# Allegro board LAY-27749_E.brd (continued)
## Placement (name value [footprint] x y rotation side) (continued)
R767  4.7K  [RC0402_25]  85.98 139.06 90 bottom
R768  4.7K  [RC0402_25]  85.09 139.06 90 bottom
R769  5.1  [RC0402_25]  80.77 138.28 90 bottom
R770  5.1  [RC0402_25]  116.08 138.18 180 bottom
R771  4.7K  [RC0402_25]  85.98 136.65 90 bottom
R772  4.7K  [RC0402_25]  85.09 136.65 90 bottom
R796  4.7K  [RC0402_25]  82.93 124.97 0 top
R816  0  [RC0402_25]  72.9 30.61 270 top
R817  0  [RC0603_OV]  52.78 30.61 270 top
R818  4.7K  [RC0402_25]  102.49 88.32 270 bottom
R830  10.0K  [RC0402_25]  244.6 211.84 180 bottom
R922  10.0K  [RC0402_25]  217.73 33.53 270 bottom
R923  1.5K  [RC0402_25]  218.74 33.53 90 bottom
R924  1.5K  [RC0402_25]  216.71 33.53 90 bottom
R925  10.0K  [RC0402_25]  214.68 33.53 270 bottom
R926  1.5K  [RC0402_25]  219.76 33.53 270 bottom
R927  1.5K  [RC0402_25]  215.7 33.53 270 bottom
R928  0  [RC0402_25]  213.66 33.53 270 bottom
R930  100  [RC0402_25]  212.65 33.53 270 bottom
R931  10.0K  [RC0402_25]  231.98 33.53 270 bottom
R932  1.5K  [RC0402_25]  232.99 33.53 90 bottom
R933  1.5K  [RC0402_25]  230.96 33.53 90 bottom
R934  10.0K  [RC0402_25]  228.93 33.53 270 bottom
R935  1.5K  [RC0402_25]  234.01 33.53 270 bottom
R936  1.5K  [RC0402_25]  229.94 33.53 270 bottom
R937  0  [RC0402_25]  227.91 33.53 270 bottom
R938  10.0K  [RC0402_25]  225.88 33.53 270 bottom
R939  100  [RC0402_25]  226.9 33.53 270 bottom
R940  10.0K  [RC0402_25]  246.23 33.53 270 bottom
R941  1.5K  [RC0402_25]  247.24 33.53 90 bottom
R942  1.5K  [RC0402_25]  245.21 33.53 90 bottom
R943  10.0K  [RC0402_25]  243.18 33.53 270 bottom
R944  1.5K  [RC0402_25]  248.26 33.53 270 bottom
R945  1.5K  [RC0402_25]  244.2 33.53 270 bottom
R946  0  [RC0402_25]  242.16 33.53 270 bottom
R947  10.0K  [RC0402_25]  240.13 33.53 270 bottom
R948  100  [RC0402_25]  241.15 33.53 270 bottom
R949  10.0K  [RC0402_25]  260.48 33.53 270 bottom
R950  1.5K  [RC0402_25]  259.46 33.53 90 bottom
R951  1.5K  [RC0402_25]  261.49 33.53 90 bottom
R952  10.0K  [RC0402_25]  257.43 33.53 270 bottom
R953  1.5K  [RC0402_25]  258.44 33.53 270 bottom
R954  1.5K  [RC0402_25]  262.51 33.53 270 bottom
R955  0  [RC0402_25]  256.41 33.53 90 bottom
R956  10.0K  [RC0402_25]  254.38 33.53 270 bottom
R957  100  [RC0402_25]  255.4 33.53 270 bottom
R992  330  [RC0402_25]  271.4 14.61 270 top
R993  330  [RC0402_25]  270.13 14.61 270 top
R994  330  [RC0402_25]  200.66 14.73 270 top
R995  330  [RC0402_25]  199.26 14.73 270 top
R1052  33  [RC0402_25]  70.48 31.24 180 top
R1053  33  [RC0402_25]  68.33 31.24 180 top
R1054  33  [RC0402_25]  66.17 31.24 180 top
R1055  33  [RC0402_25]  64.01 31.24 180 top
R1056  33  [RC0402_25]  61.85 31.24 180 top
R1057  33  [RC0402_25]  59.69 31.24 180 top
R1058  33  [RC0402_25]  57.53 31.24 180 top
R1059  33  [RC0402_25]  55.37 31.24 180 top
R1082  10.0K  [RC0402_25]  211.63 33.53 270 bottom
R1969  330  [RC0402_25]  279.88 85.33 180 top
R5582  1.0  [RC0805_OV]  50.11 70.13 0 bottom
R5583  1.0K  [RC0402_HD]  52.1 76.83 0 top
R5584  1.0K  [RC0402_HD]  13.32 69.39 90 bottom
R5585  1.0K  [RC0402_HD]  1.99 77.01 90 bottom
R5588  10.0K  [RC0402_25]  48.9 58.9 270 top
R5589  10.0K  [RC0402_25]  36.4 56.87 0 top
R5667  1.0K  [RC0402_HD]  49.15 70.13 90 top
R5671  1.0K  [RC0402_HD]  52.1 75.69 0 top
R5680  10.0K  [RC0402_25]  191.26 43.92 0 top
R5681  10.0K  [RC0402_25]  135.89 244.6 90 top
R5682  10.0K  [RC0402_25]  33.78 244.6 90 top
R5683  10.0K  [RC0402_25]  55.75 244.6 90 top
R5684  10.0K  [RC0402_25]  2.03 244.6 90 top
R5685  10.0K  [RC0402_25]  191.26 45.58 180 top
R5686  10.0K  [RC0402_25]  137.41 244.6 270 top
R5687  10.0K  [RC0402_25]  35.43 244.6 270 top
R5688  10.0K  [RC0402_25]  57.28 244.6 270 top
R5689  10.0K  [RC0402_25]  3.56 244.6 270 top
R5690  33K  [RC0402_25]  247.1 216.15 90 top
R5691  10.0K  [RC0402_25]  189.29 45.58 0 top
R5692  10.0K  [RC0402_25]  137.41 242.57 90 top
R5693  10.0K  [RC0402_25]  35.43 242.57 90 top
R5694  10.0K  [RC0402_25]  57.28 242.57 90 top
R5695  10.0K  [RC0402_25]  3.56 242.57 90 top
R5698  4.7K  [RC0402_25]  250.02 219.64 0 top
R5699  4.7K  [RC0402_25]  250.02 221.23 0 top
R5700  4.7K  [RC0402_25]  246.98 223.9 90 top
R5701  4.7K  [RC0402_25]  241.77 220.29 180 top
R5702  4.7K  [RC0402_25]  241.77 218.82 180 top
R5703  10.0K  [RC0402_25]  89.45 72.16 90 top
R5704  4.7K  [RC0402_25]  130.12 84.11 180 bottom
R5705  4.7K  [RC0402_25]  117.55 88.67 270 bottom
R5706  4.7K  [RC0402_25]  116.54 88.67 270 bottom
R5707  19.1  [RC0402_25]  120.73 77 270 top
R5708  19.1  [RC0402_25]  130.12 88.98 0 top
R5710  4.7K  [RC0402_25]  118.82 81.94 90 bottom
R5711  4.7K  [RC0402_25]  120.22 81.94 90 bottom
R5712  4.7K  [RC0402_25]  119.33 84.48 0 bottom
R5713  19.1  [RC0402_25]  120.98 92.61 90 top
R5721  1K  [RC0402_25]  106.02 110.53 90 top
R5722  19.1  [RC0402_25]  130.13 80.64 0 top
R5724  19.1  [RC0402_25]  117.42 92.43 90 top
R5725  17.4K  [RC0402_25]  33.15 40.39 180 top
R5726  19.1  [RC0402_25]  130.12 87.98 0 top
R5727  4.7K  [RC0402_25]  36.32 87.5 270 top
R5728  4.7K  [RC0402_25]  28.17 87.63 270 top
R5729  4.7K  [RC0402_25]  34.42 79.89 270 top
R5730  10.0K  [RC0402_25]  28.82 105.5 90 top
R5731  20K  [RC0402_25]  30.2 104.95 0 top
R5734  0  [RC0402_25]  170.46 116.2 90 top
R5735  0  [RC0402_25]  39.99 190 270 top
R5736  10.0  [RC0402_25]  32.43 162.93 90 top
R5737  12.4K  [RC0402_25]  27.39 166.57 90 top
R5739  17.4K  [RC0402_25]  28.78 166.01 0 top
R5740  10.0  [RC0402_25]  34.03 138.32 90 top
R5747  20K  [RC0402_25]  37.06 129.2 270 top
R5748  10.0K  [RC0402_25]  38.09 129.2 90 top
R5751  5K  [RC0402_25]  137.67 45.4 90 bottom
R5753  4.7K  [RC0402_25]  137.54 50.67 270 bottom
R5754  4.7K  [RC0402_25]  138.43 50.67 90 bottom
R5755  4.7K  [RC0402_25]  135.65 49.15 0 bottom
R5762  4.7K  [RC0402_25]  92.58 139.06 270 bottom
R5763  10.0  [RC0402_25]  204.81 66.01 180 top
R5766  20K  [RC0402_25]  201.18 60.97 180 top
R5767  10.0K  [RC0402_25]  201.73 62.36 90 top
R5768  10.0K  [RC0402_25]  37.06 124.07 0 top
R5769  4.7K  [RC0402_25]  56.03 84.73 90 top
R5770  4.7K  [RC0402_25]  57.35 84.73 90 top
R5771  4.7K  [RC0402_25]  82.93 123.95 180 top
R5772  10.0K  [RC0402_25]  261.24 144.53 0 top
R5773  10.0K  [RC0402_25]  261.24 145.8 0 top
R5774  10.0K  [RC0402_25]  261.24 147.07 0 top
R5775  10.0K  [RC0402_25]  261.24 148.34 0 top
R5776  10.0K  [RC0402_25]  261.24 155.45 0 top
R5777  10.0K  [RC0402_25]  261.24 156.72 0 top
R5778  10.0K  [RC0402_25]  261.24 157.99 0 top
R5779  10.0K  [RC0402_25]  261.24 159.26 0 top
R5780  10.0K  [RC0402_25]  261.24 166.37 0 top
R5781  10.0K  [RC0402_25]  261.24 167.64 0 top
R5782  10.0K  [RC0402_25]  261.24 168.91 0 top
R5783  10.0K  [RC0402_25]  261.24 170.18 0 top
R5784  10.0K  [RC0402_25]  261.24 177.29 0 top
R5785  10.0K  [RC0402_25]  261.24 178.56 0 top
R5786  10.0K  [RC0402_25]  261.24 179.83 0 top
R5787  10.0K  [RC0402_25]  261.24 181.1 0 top
R5788  33  [RC0402_25]  183.9 191.13 180 top
R5789  33  [RC0402_25]  34.68 198.75 270 top
R5790  10.0K  [RC0402_25]  245.71 223.9 270 top
R5791  0  [RC0402_25]  119.39 50.11 180 bottom
R5792  0  [RC0402_25]  161.56 50.11 180 bottom
R5793  0  [RC0402_25]  117.07 46.99 180 bottom
R5794  0  [RC0402_25]  119.11 46.23 180 bottom
R5795  0  [RC0402_25]  116.9 44.87 90 bottom
R5796  0  [RC0402_25]  114.11 44.92 0 bottom
R5797  0  [RC0402_25]  156.26 46.33 0 bottom
R5798  0  [RC0402_25]  161.27 46.23 180 bottom
R5799  0  [RC0402_25]  159.07 44.87 90 bottom
R5800  0  [RC0402_25]  156.27 44.92 0 bottom
R5801  10.0  [RC0402_25]  249.21 90.77 180 top
R5802  4.7K  [RC0402_25]  179.71 50.67 270 bottom
R5803  4.7K  [RC0402_25]  177.81 49.15 0 bottom
R5804  4.7K  [RC0402_25]  180.67 50.67 90 bottom
R5805  5K  [RC0402_25]  179.83 45.4 90 bottom
R5806  4.32K  [RC0402_25]  78.05 222.66 180 bottom
R5807  7.32K  [RC0402_25]  76.28 226.82 0 bottom
R5808  9.09k  [RC0402_25]  78.05 223.8 180 bottom
R5809  7.32K  [RC0402_25]  78.69 226.82 180 bottom
R5810  11.3K  [RC0402_25]  80.85 227.23 0 top
R5811  1.0K  [RC0402_HD]  98.94 228.97 180 top
R5812  1.0K  [RC0402_HD]  98.94 228.01 180 top
R5813  0  [RC0603_OV]  102.28 226.57 0 bottom
R5814  2.67K  [RC0402_25]  68.65 222.36 180 top
R5815  10.0K  [RC0402_25]  181.62 99.84 270 top
R5816  0  [RC0402_25]  199.53 97.56 270 top
R5817  1K  [RC0402_25]  200.77 97.56 90 bottom
R5818  1K  [RC0402_25]  197.5 97.56 270 top
R5819  1K  [RC0402_25]  197.32 114.42 90 top
R5820  1K  [RC0402_25]  201.29 114.42 90 top
R5825  1K  [RC0402_25]  183.95 82.98 90 bottom
R5826  1K  [RC0402_25]  180.67 83.01 90 bottom
R5827  1K  [RC0402_25]  180.49 99.84 270 bottom
R5828  1K  [RC0402_25]  184.46 99.84 270 bottom
R5829  1K  [RC0402_25]  183.95 82.98 270 top
R5830  1K  [RC0402_25]  180.67 83.01 270 top
R5831  1K  [RC0402_25]  180.49 99.84 90 top
R5832  1K  [RC0402_25]  184.46 99.84 90 top
R5837  1K  [RC0402_25]  200.77 97.56 270 top
R5838  1K  [RC0402_25]  197.5 97.58 90 bottom
R5839  1K  [RC0402_25]  197.32 114.42 270 bottom
R5840  1K  [RC0402_25]  201.29 114.42 270 bottom
R5847  19.1  [RC0402_25]  125.29 92.54 90 top
R5848  19.1  [RC0402_25]  126.4 92.54 90 top
R5849  19.1  [RC0402_25]  126.66 77 270 top
R5850  19.1  [RC0402_25]  125.56 77 270 top
R5851  49.9K  [RC0402_25]  95.68 37.31 0 top
R5852  49.9K  [RC0402_25]  78.53 37.08 180 top
R5853  4.7K  [RC0402_25]  69.93 144.6 0 top
R5854  4.7K  [RC0402_25]  70.09 149.35 0 top
R5855  4.7K  [RC0402_25]  70.09 148.21 0 top
R5856  4.7K  [RC0402_25]  70.09 145.92 0 top
R5857  4.7K  [RC0402_25]  70.09 147.07 0 top
R5858  10.0K  [RC0402_25]  82.95 96.42 270 top
R5870  4.7K  [RC0402_25]  241.47 120.53 90 top
R5871  4.7K  [RC0402_25]  244.74 120.53 90 top
R5872  4.7K  [RC0402_25]  241.15 132.59 270 top
R5873  4.7K  [RC0402_25]  237.87 132.59 270 top
R5874  4.7K  [RC0402_25]  238.96 132.59 270 top
R5875  10.0K  [RC0402_25]  112.65 139.06 270 bottom
R5876  200  [RC0402_25]  109.33 143.69 180 bottom
R5877  200  [RC0402_25]  109.35 144.69 180 bottom
R5878  200  [RC0402_25]  106.33 141.69 0 bottom
R5879  200  [RC0402_25]  106.33 142.69 0 bottom
R5880  200  [RC0402_25]  105.33 143.7 0 bottom
R5881  200  [RC0402_25]  105.33 144.69 0 bottom
R5882  200  [RC0402_25]  105.92 138.43 90 bottom
R5883  200  [RC0402_25]  104.9 138.43 90 bottom
R5884  200  [RC0402_25]  91.33 181.69 0 bottom
R5885  200  [RC0402_25]  91.33 180.7 0 bottom
R5886  200  [RC0402_25]  92.33 183.69 180 bottom
R5887  200  [RC0402_25]  92.33 182.73 180 bottom
R5888  200  [RC0402_25]  90.33 183.69 180 bottom
R5889  200  [RC0402_25]  90.33 182.73 180 bottom
R5890  200  [RC0402_25]  105.83 154.2 270 bottom
R5891  200  [RC0402_25]  104.81 153.19 270 bottom
R5892  10.0K  [RC0402_25]  244.56 223.9 270 top
R5893  9.88K  [RC0402_25]  30.38 141.4 0 top
R5894  12.4K  [RC0402_25]  28.99 141.95 270 top
R5895  0  [RC0402_25]  103.03 95.23 90 top
R5896  0  [RC0402_25]  114.98 95.67 270 top
R5897  4.7K  [RC0402_25]  58.8 84.73 90 top
R5898  4.7K  [RC0402_25]  81.28 124.46 90 top
R5902  4.7K  [RC0402_25]  80.01 124.46 90 top
R5903  4.7K  [RC0402_25]  78.61 124.46 90 top
R5904  4.7K  [RC0402_25]  77.34 124.46 90 top
R5905  0  [RC0402_25]  170.46 114.17 90 top
R5906  0  [RC0402_25]  41.66 190.5 180 top
R5907  4.7K  [RC0402_25]  273.41 76.92 270 top
SW1  416131160804  [SW4_DIP_1P27_6P3X5P7]  267.46 146.43 90 top
SW2  416131160804  [SW4_DIP_1P27_6P3X5P7]  267.46 157.35 90 top
SW3  416131160804  [SW4_DIP_1P27_6P3X5P7]  267.46 168.28 90 top
SW4  416131160804  [SW4_DIP_1P27_6P3X5P7]  267.46 179.2 90 top
SW5  SPL6BLH  [SW6_TACT_LED_TH]  17.75 17.3 90 top
SW6  TL1105SF160Q  [SW2_TL1105S]  5.76 3.72 0 top
TP1  TPAD_020  [TPAD_020_TOP]  76.33 154.94 90 top
TP2  TPAD_020  [TPAD_020_TOP]  75.31 153.8 90 top
TP3  TPAD_020  [TPAD_020_TOP]  75.84 151.79 90 top
TP4  TPAD_020  [TPAD_020_TOP]  71.92 151.17 90 top
TP5  TPAD_020  [TPAD_020_TOP]  74.42 150.83 0 top
TP6  TPAD_020  [TPAD_020_TOP]  68.45 148.84 0 top
TP7  TPAD_020  [TPAD_020_TOP]  68.45 147.57 0 top
TP8  TPAD_020  [TPAD_020_TOP]  68.45 146.43 0 top
TP9  TPAD_020  [TPAD_020_TOP]  68.45 145.29 0 top
TP10  TPAD_020  [TPAD_020_TOP]  75.69 148.84 0 top
TP11  TPAD_020  [TPAD_020_TOP]  74.55 148.84 0 top
TP13  TPAD_020  [TPAD_020_TOP]  74.3 143.76 90 top
TP14  TPAD_020  [TPAD_020_TOP]  75.69 143.76 0 top
TP15  TPAD_020  [TPAD_020_TOP]  80.9 138.94 0 top
TP16  TPAD_020  [TPAD_020_TOP]  82.17 138.94 0 top
TP18  TPAD_020  [TPAD_020_TOP]  87.12 138.94 90 top
TP19  TPAD_020  [TPAD_020_TOP]  88.39 138.94 0 top
TP20  TPAD_020  [TPAD_020_TOP]  80.9 137.54 0 top
TP21  TPAD_020  [TPAD_020_TOP]  82.17 137.54 0 top
TP22  TPAD_020  [TPAD_020_TOP]  84.07 137.54 0 top
TP72  TPAD_020  [TPAD_020_TOP]  80.9 42.75 0 top
TP73  TPAD_020  [TPAD_020_TOP]  95.82 174.69 180 bottom
TP74  TPAD_020  [TPAD_020_TOP]  90.81 174.69 0 bottom
TP75  TPAD_020  [TPAD_020_TOP]  104.84 173.74 90 bottom
TP76  TPAD_020  [TPAD_020_TOP]  101.85 173.74 90 bottom
TP77  TPAD_020  [TPAD_020_TOP]  99.82 173.74 0 bottom
TP78  TPAD_020  [TPAD_020_TOP]  108.84 173.69 180 bottom
TP79  TPAD_020  [TPAD_020_TOP]  96.84 173.67 270 bottom
TP80  TPAD_020  [TPAD_020_TOP]  94.81 173.67 180 bottom
TP81  TPAD_020  [TPAD_020_TOP]  92.84 173.67 180 bottom
TP82  TPAD_020  [TPAD_020_TOP]  109.86 172.69 180 bottom
TP83  TPAD_020  [TPAD_020_TOP]  89.79 166.7 180 bottom
TP84  TPAD_020  [TPAD_020_TOP]  89.82 158.69 180 bottom
TP86  TPAD_020  [TPAD_020_TOP]  79.96 153.85 180 bottom
TP88  TPAD_020  [TPAD_020_TOP]  106.32 148.54 180 bottom
TP89  TPAD_020  [TPAD_020_TOP]  94.81 152.72 180 bottom
TP90  TPAD_020  [TPAD_020_TOP]  108.84 152.65 270 bottom
TP91  TPAD_020  [TPAD_020_TOP]  106.82 151.7 180 bottom
TP92  TPAD_020  [TPAD_020_TOP]  103.82 151.7 180 bottom
TP93  TPAD_020  [TPAD_020_TOP]  97.92 151.69 180 bottom
TP94  TPAD_020  [TPAD_020_TOP]  95.89 151.69 180 bottom
TP95  TPAD_020  [TPAD_020_TOP]  100.84 151.64 180 bottom
TP96  TPAD_020  [TPAD_020_TOP]  110.81 150.69 270 bottom
TP97  TPAD_020  [TPAD_020_TOP]  93.79 150.74 180 bottom
TP98  TPAD_020  [TPAD_020_TOP]  111.82 149.73 270 bottom
TP99  TPAD_020  [TPAD_020_TOP]  109.86 149.67 270 bottom
TP100  TPAD_020  [TPAD_020_TOP]  108.84 146.69 180 bottom
TP101  TPAD_020  [TPAD_020_TOP]  85.86 145.67 180 bottom
TP103  TPAD_020  [TPAD_020_TOP]  86.74 142.49 180 bottom
TP115  TPAD_020  [TPAD_020_TOP]  276.32 84.57 0 top
TP192  TPAD_020  [TPAD_020_TOP]  47.93 74.47 0 top
TP193  TPAD_020  [TPAD_020_TOP]  49.2 71.93 0 top
TP194  TPAD_020  [TPAD_020_TOP]  47.93 73.2 0 top
TP195  TPAD_020  [TPAD_020_TOP]  49.2 73.2 0 top
TP196  TPAD_020  [TPAD_020_TOP]  62.03 65.84 0 top
TP197  TPAD_020  [TPAD_020_TOP]  47.93 71.93 0 top
TP200  TPAD_020  [TPAD_020_TOP]  79.38 100.3 90 top
TP201  TPAD_020  [TPAD_020_TOP]  80.04 101.42 90 top
TP202  TPAD_020  [TPAD_020_TOP]  80.75 100.3 90 top
TP203  TPAD_020  [TPAD_020_TOP]  81.41 101.42 90 top
TP204  TPAD_020  [TPAD_020_TOP]  82.12 100.3 90 top
TP205  TPAD_020  [TPAD_020_TOP]  86.87 145.8 180 bottom
TP206  TPAD_020  [TPAD_020_TOP]  93.34 137.01 180 bottom
TP208  TPAD_020  [TPAD_020_TOP]  127.97 90.07 0 top
TP209  TPAD_020  [TPAD_020_TOP]  118.75 73.81 0 top
TP210  TPAD_020  [TPAD_020_TOP]  115.27 89.05 0 top
TP212  TPAD_020  [TPAD_020_TOP]  113.51 107.29 0 top
TP213  TPAD_020  [TPAD_020_TOP]  72.39 148.92 0 top
TP214  TPAD_020  [TPAD_020_TOP]  129.12 90.02 0 top
TP215  TPAD_020  [TPAD_020_TOP]  23.16 232.82 0 top
TP216  TPAD_020  [TPAD_020_TOP]  24.81 234.09 0 top
TP217  TPAD_020  [TPAD_020_TOP]  30 99.44 0 top
TP218  TPAD_020  [TPAD_020_TOP]  28.57 160.5 0 top
TP219  TPAD_020  [TPAD_020_TOP]  30.18 135.89 0 top
TP222  TPAD_020  [TPAD_020_TOP]  93.17 83.39 0 top
TP223  TPAD_020  [TPAD_020_TOP]  140.19 46.93 180 top
TP224  TPAD_020  [TPAD_020_TOP]  140.72 45.84 180 top
TP225  TPAD_020  [TPAD_020_TOP]  140.19 50.93 180 top
TP226  TPAD_020  [TPAD_020_TOP]  140.19 52.7 180 top
TP227  TPAD_020  [TPAD_020_TOP]  140.95 54.01 180 top
TP228  TPAD_020  [TPAD_020_TOP]  140.95 51.83 180 top
TP229  TPAD_020  [TPAD_020_TOP]  140.19 54.86 180 top
TP230  TPAD_020  [TPAD_020_TOP]  118.97 60.68 180 top
TP231  TPAD_020  [TPAD_020_TOP]  118.63 59.27 180 top
TP232  TPAD_020  [TPAD_020_TOP]  117.99 60.26 180 top
TP233  TPAD_020  [TPAD_020_TOP]  114.54 56.04 180 top
TP234  TPAD_020  [TPAD_020_TOP]  114.54 52.87 180 top
TP235  TPAD_020  [TPAD_020_TOP]  113.65 53.53 180 top
TP236  TPAD_020  [TPAD_020_TOP]  114.54 54.29 180 top
TP237  TPAD_020  [TPAD_020_TOP]  113.65 54.98 180 top
TP238  TPAD_020  [TPAD_020_TOP]  114.54 49.29 180 top
TP239  TPAD_020  [TPAD_020_TOP]  113.65 50.07 180 top
TP240  TPAD_020  [TPAD_020_TOP]  114.54 51.16 180 top
TP241  TPAD_020  [TPAD_020_TOP]  113.65 51.91 180 top
TP242  TPAD_020  [TPAD_020_TOP]  114.54 46.74 180 top
TP243  TPAD_020  [TPAD_020_TOP]  113.65 47.33 180 top
TP244  TPAD_020  [TPAD_020_TOP]  114.54 47.97 180 top
TP245  TPAD_020  [TPAD_020_TOP]  113.54 48.92 180 top
TP246  TPAD_020  [TPAD_020_TOP]  207.24 62.16 90 top
TP249  TPAD_020  [TPAD_020_TOP]  248.52 156.64 0 top
TP252  TPAD_020  [TPAD_020_TOP]  78.45 103.43 90 top
TP253  TPAD_020  [TPAD_020_TOP]  72.73 103.43 90 top
TP254  TPAD_020  [TPAD_020_TOP]  73.91 103.43 90 top
TP255  TPAD_020  [TPAD_020_TOP]  75.02 103.43 90 top
TP256  TPAD_020  [TPAD_020_TOP]  76.16 103.43 90 top
TP257  TPAD_020  [TPAD_020_TOP]  77.3 103.43 90 top
TP258  TPAD_020  [TPAD_020_TOP]  81.19 134.7 90 top
TP259  TPAD_020  [TPAD_020_TOP]  65.79 83.44 0 top
TP260  TPAD_020  [TPAD_020_TOP]  251.64 86.92 90 top
TP261  TPAD_020  [TPAD_020_TOP]  182.35 46.93 180 top
TP262  TPAD_020  [TPAD_020_TOP]  182.88 45.84 180 top
TP263  TPAD_020  [TPAD_020_TOP]  182.35 50.93 180 top
TP264  TPAD_020  [TPAD_020_TOP]  182.35 52.7 180 top
TP265  TPAD_020  [TPAD_020_TOP]  183.12 54.01 180 top
TP266  TPAD_020  [TPAD_020_TOP]  183.12 51.83 180 top
TP267  TPAD_020  [TPAD_020_TOP]  182.35 54.86 180 top
TP268  TPAD_020  [TPAD_020_TOP]  156.7 46.74 180 top
TP269  TPAD_020  [TPAD_020_TOP]  155.81 47.33 180 top
TP270  TPAD_020  [TPAD_020_TOP]  156.7 47.97 180 top
TP271  TPAD_020  [TPAD_020_TOP]  155.68 48.82 180 top
TP272  TPAD_020  [TPAD_020_TOP]  156.7 49.29 180 top
TP273  TPAD_020  [TPAD_020_TOP]  155.81 50.07 180 top
TP274  TPAD_020  [TPAD_020_TOP]  156.7 51.16 180 top
TP275  TPAD_020  [TPAD_020_TOP]  155.81 51.85 180 top
TP276  TPAD_020  [TPAD_020_TOP]  156.7 52.87 180 top
TP277  TPAD_020  [TPAD_020_TOP]  155.81 53.53 180 top
TP278  TPAD_020  [TPAD_020_TOP]  156.7 54.29 180 top
TP279  TPAD_020  [TPAD_020_TOP]  155.81 54.98 180 top
TP280  TPAD_020  [TPAD_020_TOP]  156.7 56.04 180 top
TP281  TPAD_020  [TPAD_020_TOP]  160.15 60.26 180 top
TP282  TPAD_020  [TPAD_020_TOP]  160.79 59.27 180 top
TP283  TPAD_020  [TPAD_020_TOP]  161.14 60.68 180 top
TP284  TPAD_020  [TPAD_020_TOP]  112.09 141.55 180 bottom
TP285  TPAD_020  [TPAD_020_TOP]  112.65 140.67 180 bottom
TP286  TPAD_020  [TPAD_020_TOP]  132.92 237.52 0 top
TP287  TPAD_020  [TPAD_020_TOP]  108.52 95.22 90 top
TP288  TPAD_020  [TPAD_020_TOP]  109.49 95.68 270 top
TP289  TPAD_020  [TPAD_020_TOP]  275.18 84.57 0 top
TP290  TPAD_020  [TPAD_020_TOP]  50.24 68.2 0 top
U1  AP62600SJ-7  [QFN12_0P5_2P05X3P05MM]  31.04 102.16 180 top
U2  ADT7481ARMZ  [MSOP10_60X12]  249.05 232.92 0 top
U3  LTC3882  [QFN40_0P5_6P1X6P1]  83.39 222.66 90 bottom
U7  SIC620ACD-T1-GE3  [POWERPAK_MLP55]  94.43 230.99 180 top
U9  SIC620ACD-T1-GE3  [POWERPAK_MLP55]  76.35 231.36 180 top
U14  MP20073DH  [MSOP8_0P65_3P1X3P1_EPAD]  34.54 194.18 90 top
U16  PCF2131  [SO16_0P5_3P5X4P5_MM]  277.34 81.02 270 top
U17  MP20073DH  [MSOP8_0P65_3P1X3P1_EPAD]  179.33 191.27 0 top
U18  PCA9517ADP  [TSSOP8_A]  246.63 204.6 180 top
U22  T4240NSE7TTB  [BGA1932_1MM_45X45MM]  100.33 163.19 180 top
U23  AP62600SJ-7  [QFN12_0P5_2P05X3P05MM]  29.62 163.22 180 top
U25  AP62600SJ-7  [QFN12_0P5_2P05X3P05MM]  31.22 138.61 180 top
U26  SST25WF040B  [SO8_1P27_4X5]  86.16 132.41 180 top
U27  M2GL005-VFG256  [BGA256_0P8_14X14MM_C016S]  61.07 74.8 180 top
U32  SI53258  [QFN40_0P5_6X6_4P6EP]  108.2 105.23 180 top
U36  Si5341B-D15390-GM  [QFN64_0P5_9X9C]  122 84.73 0 top
U37  S29GL01GT11TFIV10  [TSOP56_0P5_14X18]  84.2 84.2 270 top
U38  MT29F8G08ABBCAH4-IT:C  [VFBGA63_0P8_9X11]  99.69 83.82 0 top
U42  88E1543A1LKJ2C000T123  [LQFP128_0P5_20X14_EPAD]  127.38 49.66 0 top
U45  NVT4858HK  [XQFN16_0P4_2P7X1P9]  83.82 42.37 180 top
U46  LTC2804  [DFN16_0P5_3X5]  66.29 36.57 90 top
U47  NX5P3090UK  [WLCSP12_0P4_1P38X1P68MM_SMDP]  43.18 42.04 270 top
U48  NX5P3090UK  [WLCSP12_0P4_1P38X1P68MM_SMDP]  33.15 42.04 270 top
U55  PCIE-LP-04-01-F-DV-A-K-TR  [CON64_1MM_SM_PCIE_LP]  221.72 215.15 270 top
U58  PCA9517ADP  [TSSOP8_A]  246.51 210.82 180 top
U65  DS100DF410  [QFN48_0P5_7X7_EP5P1]  182.37 90.81 180 top
U68  AP62600SJ-7  [QFN12_0P5_2P05X3P05MM]  248.92 87.96 270 top
U69  AP62600SJ-7  [QFN12_0P5_2P05X3P05MM]  204.52 63.2 270 top
U82  PCA9547PW  [TSSOP24_0P65_7P9X4P5]  240.05 126.5 90 top
U95  LTC2804  [DFN16_0P5_3X5]  57.66 36.63 90 top
U105  EMC2305  [TQFN16_0P65_4X4MM_TAB]  245.96 219.96 0 top
U250  SST25LF080  [SO8-25X75-200]  42.98 57.51 270 top
U589  24AA025UID-I/SN  [SO8_1P27_4X5]  246.68 197.23 180 top
U593  74ALVCH16373DGGRG4  [TSSOP48_PH]  86.77 110.79 90 top
U594  74ALVCH16373DGGRG4  [TSSOP48_PH]  72.03 110.79 90 top
U595  74LVC1G86GW-Q100  [SC70-5]  90.35 101.24 180 top
U596  74LVC1G86GW-Q100  [SC70-5]  87.38 101.24 180 top
U598  74LVC1G86GW-Q100  [SC70-5]  84.37 101.24 180 top
U605  RT9013-33GQW  [DFN6_0P65_2X2_EP]  35.05 84.96 180 top
U606  RT9013-18GB  [SOT-23-5]  29.31 84.58 180 top
U607  RT9078-12GJ5_5P  [SOT23-5]  35.56 76.58 180 top
U608  PUSB3AB4  [XSON10_0P5_1P1X2P6MM]  42.02 17.14 90 top
U610  PCA9701  [TSSOP_24_0P65_8X4]  253.23 162.91 90 top
U620  88E1543A1LKJ2C000T123  [LQFP128_0P5_20X14_EPAD]  169.54 49.66 0 top
U622  DS100DF410  [QFN48_0P5_7X7_EP5P1]  199.2 105.38 180 top
U624  PCA9671BS  [QFN24_4X4_EP2P25MM]  250.27 111.68 180 top
U625  24AA025UID-I/SN  [SO8_1P27_4X5]  246.63 190.75 180 top
U626  SI53361-B-GM  [QFN16_0P5_3X3MM]  105.69 95.47 90 top
U627  SI53361-B-GM  [QFN16_0P5_3X3MM]  112.32 95.43 270 top
U628  74AUP1G04GV  [SOT23-5_A]  44.45 46.99 90 top
U629  74AUP1G04GV  [SOT23-5_A]  34.42 46.99 90 top
U630  MAX8902B  [TDFN8_1P98_2P10X2P10]  36.31 126.33 90 top
U631  LTC7150S  [BGA42_0P8_5X6]  28.29 228.47 0 top
Y7  7M48072002  [XTAL_4_3P3X2P6MM]  112.85 85.24 270 top
Y19  16MHz  [XTAL4_2P1X1P7]  50.88 80.77 90 top
Y20  25MHZ  [XTAL2_3P3X2P6]  143.64 48.65 90 top
Y21  25MHZ  [XTAL2_3P3X2P6]  185.8 48.65 90 top

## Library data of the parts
BH9 BH10 = MOUNT_HOLE: room: VDD_GVDD_PS
C1-C6 C8-C10 C12 C15-C18 C83 C84 C89 C105 C120-C123 C125 C133-C136 C143 C148 C151 C169 C170 C173 C199 C205 C207 C250 C252 C253 C256 C258-C263 C265 C268-C271 C273-C275 C280-C286 C288 C305 C334 C341 C412 C434 C467 C472 C485 C546-C557 C562-C573 C588 C592 C604 C607-C611 C614 C616-C620 C624 C627 C628 C638 C650 C691 C709 C710 C715-C717 C728 C782 C800 C802 C821 C822 C833 C837 C839 C841-C845 C847 C859 C860 C867 C868 C871 C877-C880 C900 C987 C991-C993 C1002 C1109-C1113 C1141-C1152 C1224-C1227 C1229-C1232 C1240-C1243 C1247 C1250-C1254 C1256 C1257 C1259-C1266 C2673 C2679 C2680 C3690 C3691 C3744 C3745 C3844 C3847 C3849-C3856 C3860-C3870 C3889-C3892 C3894 C3895 C3897-C3900 C5116-C5121 C5125 C5126 C5131 C5133 C5134 C5136-C5168 C5171 C5174-C5176 C5178-C5211 C5213-C5259 C5270-C5272 C5302-C5309 C5312-C5321 C5327-C5330 C5333 C5334 = CAP_NP
C7 C25-C28 C35 C40-C43 C58 C60 C65 C66 C76 C78-C82 C88 C90 C95 C96 C102-C104 C106 C108 C112 C113 C117-C119 C126 C128-C130 C137 C141 C144 C145 C147 C149 C152 C153 C158 C159 C162-C168 C171 C172 C176 C179 C182 C185-C187 C189 C190 C197 C201 C202 C208 C211 C215 C216 C220 C221 C224-C231 C240 C255 C276 C296 C297 C299 C300 C303 C304 C309 C310 C332 C345-C347 C433 C443-C458 C481 C482 C505 C515 C516 C518-C520 C522 C523 C574 C575 C578 C586 C594 C615 C629-C631 C635 C640-C642 C647-C649 C653 C656 C658-C664 C666 C667 C669-C676 C678 C679 C681-C688 C690 C694-C701 C703 C704 C706 C707 C711-C713 C720-C726 C729-C737 C744-C752 C754 C756-C764 C770-C781 C788-C796 C804-C806 C819 C825 C827 C828 C831 C832 C834 C838 C840 C848 C869 C924 C932 C936 C940 C944 C947 C950 C961 C965 C996-C1001 C1031-C1038 = CAP_NP: signal model: M-C0402B_0.1UF/16V
C85 C94 C127 = CAP_NP: tolerance: 10%; signal model: M-C0402B_0.1UF/16V; room: VDD_GVDD_PS
C86 C87 C93 C97 C101 C124 C2636 C2637 C5260 C5269 C5273 C5274 C5276 C5285 C5286 C5343 C5344 = CAP_NP: tolerance: 10%; room: VDD_GVDD_PS
C91 C107 C5261-C5264 C5280 C5290 = CAP_NP: room: XVDD_SVDD_PS
C92 C5291 = CAP_NP: tolerance: 20%; room: FPGA
C98 C99 C115 C116 C131 C5127-C5130 C5266 C5275 C5277 C5278 C5284 C5287 C5288 = CAP_NP: room: VDD_GVDD_PS
C109 C110 C5292-C5301 = CAP_NP: tolerance: 10%; room: PEX_SLOTS123_REFCLK
C114 = CAP_NP: tolerance: 20%; signal model: M-C0402B_0.1UF/16V; room: FPGA
C138 C150 C157 C161 C191 C192 C196 C209 C218 C246 C251 C295 C576 C577 C579-C585 C587 C590 C591 C593 C595-C603 C605 C606 C612 C613 C621-C623 C625 C626 C632-C634 C636 C637 C639 C643-C646 C651 C652 C654 C655 C657 C665 C668 C677 C680 C689 C692 C693 C702 C705 C708 C714 C718 C719 C727 C741-C743 C753 C755 C765 C766 C786 C787 C801 C803 C807-C813 C817 C818 C823 C824 C829 C830 C835 C836 C846 C849-C858 C861-C866 C870 C872-C876 = CAP_NP: signal model: M-C0402_0.1UF
C254 C5135 = CAP_NP: tolerance: 10%
C402 C406 C422 C425 = CAP_NP: signal model: M-C0402_0.01UF/16V
C1158 = CAP_NP: room: DUT_CLOSE
C1208-C1223 = CAP_NP: signal model: M-C0402B_0.01UF/50V
C2704 C2705 = CAP_NP: tolerance: 10%; room: DUT_CLOSE
C3697 C3742 C3743 = CAP_NP: room: GVDD_PS
C3698-C3700 C3831 = CAP_NP: room: 1V5_SB
C3701-C3703 C3710-C3714 C3716-C3725 C3728-C3739 C3836-C3843 = CAP_NP: Tolerance: TOLERANCE; User Part Number: 150-79872; room: 1V5_SB
C3747 = CAP_NP: room: SWITCHES
C3848 = CAP_NP: alternate symbols: (CC0402_HD); room: I2C1
C3857 C3859 = CAP_NP: tolerance: 10%; room: SDHC
C3858 C3893 C3896 = CAP_NP: tolerance: 10%; room: RS232
C3873 C3874 C3881 C3882 C5310 C5311 = CAP_NP: room: MII_MUX
C5122 C5345 CT24 CT28-CT32 CT35 CT40-CT48 CT54 CT55 = CAP_POL
C5123 C5124 C5265 C5267 C5268 C5279 C5281-C5283 C5289 C5337-C5342 = CAP_POL: room: VDD_GVDD_PS
C5132 = CAP_NP: tolerance: 5%
C5324 = CAP_NP: alternate symbols: (CC0402_HD); room: XFI
CN3 = CONN_SDCARD_PUSH_PULL_9P_SH2
CN4 = CON_USB_8P_F_4SH
D9 D10 = DIODE
D46 = DIODE_SCHTKY
ESD1-ESD10 = DIODE_TVS_BIDIR
F1 = FUSE_RESETTABLE
FAN1-FAN5 FAN12 = CON_HDR_1X4
FB1 FB23 FB87 FB89-FB93 FB95-FB99 L1 L7 L54-L57 = INDUCTOR
FB9-FB12 FB16-FB20 FB24-FB26 FB47-FB56 FB101 = BEAD_FERRITE
FB38 FB70-FB72 FB81 FB84 FB86 L26 L27 L29-L32 = BEAD
FL6 = EMIFILTER_CC
FL13-FL26 = NFM18PC225B1A3
H1-H16 = MOUNTING_HOLE_ATX_6P
J2 = CONN_SHRHDR_8X2
J3 = CONN_PCI_EXPRESS_X8
J4 J55 JP7 JP8 = CONN_HDR_3X1
J5-J7 = DDR3_240P
J8 = ATX_12V_PWR_CONN8: room: ATX_POWER
J9 = CONN_PWR_12X2
J10 = CON_SATA_PLUG7
J11-J14 = RJ45_MAG_2X1_LED
J16 = CON_SFPCAGE_1X4
J69 = CONN_HDR_5X1
J105 = HTST-105-01-S-DV: room: FPGA
J106 = CON12_98414_PMBUS: room: VDD_GVDD_PS
L3 = INDUCTOR: tolerance: 20%; room: VDD_GVDD_PS
L4 L5 = ETQP6F_2P: tolerance: 10%; room: VDD_GVDD_PS
L23 L24 = 42H171000: signal model: M-CHOKE2X1_2A_90E/350MA
L52 L53 = INDUCTOR: tolerance: 20%; room: RS232
LAN1 = CON16_RJ45_JACK
LED1-LED4 = LED
LED5 LED6 = LED_DUAL_GG
Q1 Q2 = PNP: room: VDD_GVDD_PS
Q3-Q13 = NMOS_NX3008NBK
R1-R3 R55 R56 R67-R74 R93 R97 R100 R102 R113 R119 R120 R124 R125 R128 R142 R143 R145 R146 R151 R175 R178 R179 R182 R191 R197-R200 R202 R206 R211 R213 R217-R219 R221 R222 R224 R229 R230 R232-R234 R250-R255 R257-R271 R273 R276-R280 R285 R291 R294 R295 R297-R299 R306-R310 R313 R314 R317 R319-R323 R332 R333 R335-R338 R341 R508 R524 R525 R532-R539 R641-R652 R654-R656 R659-R666 R671 R672 R685-R687 R689-R691 R693-R697 R699-R701 R706-R710 R712 R714-R718 R720 R722 R725-R727 R730-R748 R750 R751 R753 R756-R759 R762-R772 R796 R816-R818 R830 R922-R928 R930-R957 R992-R995 R1052-R1059 R1082 R5690 R5703 R5707 R5708 R5713 R5721 R5722 R5724-R5729 R5731 R5736 R5737 R5739 R5740 R5747 R5751 R5753-R5755 R5762 R5763 R5766 R5769-R5805 R5815-R5820 R5825-R5832 R5837-R5840 R5847-R5850 R5853-R5858 R5876-R5898 R5902-R5906 = RES
R30 R35 R36 R51 = RES: room: I2C1_CH2
R40 R41 R44 R57 R58 R65 R66 R76 R77 R95 R98 R99 R101 R103 R632 R5583-R5585 R5667 R5671 R5734 R5735 R5811 R5812 = RES: tolerance: 5%; room: VDD_GVDD_PS
R42 R43 R47-R50 R60-R64 R75 R78 R92 R629 R5582 R5806-R5810 R5813 R5814 = RES: room: VDD_GVDD_PS
R46 R53 R54 = RES: tolerance: 1%; room: VDD_GVDD_PS
R52 R627 R630 R631 = RES: tolerance: 5%; room: VDD_GVDD_PS; signal model: M-R0402_0E
R59 = RES: room: ATX PS
R96 R5730 R5748 R5767 R5768 R5875 = RES: room: 1V5_SB
R104 R5851 R5852 = RES: room: PS_VDD_GVDD
R176 R177 R180 R181 R311 R312 R315 R316 R318 R698 R703 R705 R711 R713 = RES: signal model: M-R0402_0
R190 R192 R196 R203 R205 R208 = RES: signal model: M-R0402B
R296 R301 = RES: signal model: M-R0402_33
R342 R637 R667 R669 R670 = RES: signal model: M-R0402_100
R394 = RES: signal model: M-R0402_27
R519-R523 R526-R528 R530 R531 R5704-R5706 R5710-R5712 R5870-R5874 = RES: tolerance: 1%; room: DUT_CLOSE
R529 = RES: tolerance: 1%; room: DUT_CLOSE; signal model: M-R0402_0E
R614 = RES: signal model: M-R0402_33E
R628 = RES: room: VDD_GVDD_PS; signal model: M-R0402_0E
R761 = RES: signal model: M-R0402_0E
R1969 = RES: tolerance: 5%
R5588 R5589 = RES: tolerance: 1%; room: FPGA
R5680-R5689 R5691-R5695 = RES: room: MII_MUX
R5698-R5702 = RES: tolerance: 1%
R5907 = RES: room: FPGA
SW1-SW4 = SW_DIP4
SW5 = SPL6BL_SW6_TACT
SW6 = SW_TACT-SPST-2_SM1
TP1-TP11 TP13-TP16 TP18-TP22 TP72-TP84 TP86 TP88-TP101 TP103 TP115 TP192-TP197 TP200-TP206 TP208-TP210 TP212-TP219 TP222-TP246 TP249 TP252-TP290 = T POINT TH
U1 U23 U25 U68 U69 = AP62600SJ
U2 = ADT7481
U3 = LTC3882_40P_EP: room: VDD_GVDD_PS
U7 U9 = SIC620ACD_MLP55
U14 U17 = MP20073DH_8P_EP
U16 = PCF2131
U18 U58 = PCA9507DP_TSSOP8
U22 = T4240
U26 = SST25WF040B_SOIC8
U27 = M2GL005_VFG256
U32 = Si53258
U36 = Si5341B_64P_EP
U37 = S29GL01GP
U38 = MT29F4G08ABBDAH4
U42 U620 = IC_88E1543_LQFP_128P_EP
U45 = NVT4858HK_QFN16
U46 U95 = LTC2804IDHC
U47 U48 = NX5P3090UK_WLCSP12
U55 = CONN_PCIEXP_64P_CUST_B
U65 U622 = DS100RT410_48P
U82 = PCA9547_24P: room: XFI
U105 = EMC2305_16P_EP
U250 = SST25LF080A
U589 U625 = 24AA025E_EEPROM_8P
U593 U594 = 74ALVCH16373DGGRG4
U595 U596 U598 = 74AUP1G86GW
U605 = RT9013_DFN6_EP
U606 = NCP561
U607 = RT9078-12GJ5_5p
U608 = DIODE_ESD_4CH_PUSB3AB4
U610 = PCA9701PW_24: room: SWITCHES
U624 = PCA9671BS_HVQFN24
U626 U627 = SI53361
U628 U629 = 74AUP1G04GV
U630 = MAX8902B: room: VDD_LP_PS
U631 = LTC7150_BGA42
Y7 = XTAL_13Y
Y19 = XTAL_13
Y20 Y21 = XTAL

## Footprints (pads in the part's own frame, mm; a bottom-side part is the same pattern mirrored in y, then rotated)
1206_CC
  rect 0.94x1.702 smd: 1(-1.4,0) 2(1.4,0)
BGA42_0P8_5X6
  round 0.406 smd: A1(-2,2.4) A2(-1.2,2.4) A3(-0.4,2.4) A4(0.4,2.4) A5(1.2,2.4) A6(2,2.4) B1(-2,1.6) B2(-1.2,1.6) B3(-0.4,1.6) B4(0.4,1.6) B5(1.2,1.6) B6(2,1.6) C1(-2,0.8) C2(-1.2,0.8) C3(-0.4,0.8) C4(0.4,0.8) C5(1.2,0.8) C6(2,0.8) D1(-2,0) D2(-1.2,0) D3(-0.4,0) D4(0.4,0) D5(1.2,0) D6(2,0) E1(-2,-0.8) E2(-1.2,-0.8) E3(-0.4,-0.8) E4(0.4,-0.8) E5(1.2,-0.8) E6(2,-0.8) F1(-2,-1.6) F2(-1.2,-1.6) F3(-0.4,-1.6) F4(0.4,-1.6) F5(1.2,-1.6) F6(2,-1.6) G1(-2,-2.4) G2(-1.2,-2.4) G3(-0.4,-2.4) G4(0.4,-2.4) G5(1.2,-2.4) G6(2,-2.4)
BGA256_0P8_14X14MM_C016S
  round 0.406 smd: A1(-6,6) A2(-5.2,6) A3(-4.4,6) A4(-3.6,6) A5(-2.8,6) A6(-2,6) A7(-1.2,6) A8(-0.4,6) A9(0.4,6) A10(1.2,6) A11(2,6) A12(2.8,6) A13(3.6,6) A14(4.4,6) A15(5.2,6) A16(6,6) B1(-6,5.2) B2(-5.2,5.2) B3(-4.4,5.2) B4(-3.6,5.2) B5(-2.8,5.2) B6(-2,5.2) B7(-1.2,5.2) B8(-0.4,5.2) B9(0.4,5.2) B10(1.2,5.2) B11(2,5.2) B12(2.8,5.2) B13(3.6,5.2) B14(4.4,5.2) B15(5.2,5.2) B16(6,5.2) C1(-6,4.4) C2(-5.2,4.4) C3(-4.4,4.4) C4(-3.6,4.4) C5(-2.8,4.4) C6(-2,4.4) C7(-1.2,4.4) C8(-0.4,4.4) C9(0.4,4.4) C10(1.2,4.4) C11(2,4.4) C12(2.8,4.4) C13(3.6,4.4) C14(4.4,4.4) C15(5.2,4.4) C16(6,4.4) D1(-6,3.6) D2(-5.2,3.6) D3(-4.4,3.6) D4(-3.6,3.6) D5(-2.8,3.6) D6(-2,3.6) D7(-1.2,3.6) D8(-0.4,3.6) D9(0.4,3.6) D10(1.2,3.6) D11(2,3.6) D12(2.8,3.6) D13(3.6,3.6) D14(4.4,3.6) D15(5.2,3.6) D16(6,3.6) E1(-6,2.8) E2(-5.2,2.8) E3(-4.4,2.8) E4(-3.6,2.8) E5(-2.8,2.8) E6(-2,2.8) E7(-1.2,2.8) E8(-0.4,2.8) E9(0.4,2.8) E10(1.2,2.8) E11(2,2.8) E12(2.8,2.8) E13(3.6,2.8) E14(4.4,2.8) E15(5.2,2.8) E16(6,2.8) F1(-6,2) F2(-5.2,2) F3(-4.4,2) F4(-3.6,2) F5(-2.8,2) F6(-2,2) F7(-1.2,2) F8(-0.4,2) F9(0.4,2) F10(1.2,2) F11(2,2) F12(2.8,2) F13(3.6,2) F14(4.4,2) F15(5.2,2) F16(6,2) G1(-6,1.2) G2(-5.2,1.2) G3(-4.4,1.2) G4(-3.6,1.2) G5(-2.8,1.2) G6(-2,1.2) G7(-1.2,1.2) G8(-0.4,1.2) G9(0.4,1.2) G10(1.2,1.2) G11(2,1.2) G12(2.8,1.2) G13(3.6,1.2) G14(4.4,1.2) G15(5.2,1.2) G16(6,1.2) H1(-6,0.4) H2(-5.2,0.4) H3(-4.4,0.4) H4(-3.6,0.4) H5(-2.8,0.4) H6(-2,0.4) H7(-1.2,0.4) H8(-0.4,0.4) H9(0.4,0.4) H10(1.2,0.4) H11(2,0.4) H12(2.8,0.4) H13(3.6,0.4) H14(4.4,0.4) H15(5.2,0.4) H16(6,0.4) J1(-6,-0.4) J2(-5.2,-0.4) J3(-4.4,-0.4) J4(-3.6,-0.4) J5(-2.8,-0.4) J6(-2,-0.4) J7(-1.2,-0.4) J8(-0.4,-0.4) J9(0.4,-0.4) J10(1.2,-0.4) J11(2,-0.4) J12(2.8,-0.4) J13(3.6,-0.4) J14(4.4,-0.4) J15(5.2,-0.4) J16(6,-0.4) K1(-6,-1.2) K2(-5.2,-1.2) K3(-4.4,-1.2) K4(-3.6,-1.2) K5(-2.8,-1.2) K6(-2,-1.2) K7(-1.2,-1.2) K8(-0.4,-1.2) K9(0.4,-1.2) K10(1.2,-1.2) K11(2,-1.2) K12(2.8,-1.2) K13(3.6,-1.2) K14(4.4,-1.2) K15(5.2,-1.2) K16(6,-1.2) L1(-6,-2) L2(-5.2,-2) L3(-4.4,-2) L4(-3.6,-2) L5(-2.8,-2) L6(-2,-2) L7(-1.2,-2) L8(-0.4,-2) L9(0.4,-2) L10(1.2,-2) L11(2,-2) L12(2.8,-2) L13(3.6,-2) L14(4.4,-2) L15(5.2,-2) L16(6,-2) M1(-6,-2.8) M2(-5.2,-2.8) M3(-4.4,-2.8) M4(-3.6,-2.8) M5(-2.8,-2.8) M6(-2,-2.8) M7(-1.2,-2.8) M8(-0.4,-2.8) M9(0.4,-2.8) M10(1.2,-2.8) M11(2,-2.8) M12(2.8,-2.8) M13(3.6,-2.8) M14(4.4,-2.8) M15(5.2,-2.8) M16(6,-2.8) N1(-6,-3.6) N2(-5.2,-3.6) N3(-4.4,-3.6) N4(-3.6,-3.6) N5(-2.8,-3.6) N6(-2,-3.6) N7(-1.2,-3.6) N8(-0.4,-3.6) N9(0.4,-3.6) N10(1.2,-3.6) N11(2,-3.6) N12(2.8,-3.6) N13(3.6,-3.6) N14(4.4,-3.6) N15(5.2,-3.6) N16(6,-3.6) P1(-6,-4.4) P2(-5.2,-4.4) P3(-4.4,-4.4) P4(-3.6,-4.4) P5(-2.8,-4.4) P6(-2,-4.4) P7(-1.2,-4.4) P8(-0.4,-4.4) P9(0.4,-4.4) P10(1.2,-4.4) P11(2,-4.4) P12(2.8,-4.4) P13(3.6,-4.4) P14(4.4,-4.4) P15(5.2,-4.4) P16(6,-4.4) R1(-6,-5.2) R2(-5.2,-5.2) R3(-4.4,-5.2) R4(-3.6,-5.2) R5(-2.8,-5.2) R6(-2,-5.2) R7(-1.2,-5.2) R8(-0.4,-5.2) R9(0.4,-5.2) R10(1.2,-5.2) R11(2,-5.2) R12(2.8,-5.2) R13(3.6,-5.2) R14(4.4,-5.2) R15(5.2,-5.2) R16(6,-5.2) T1(-6,-6) T2(-5.2,-6) T3(-4.4,-6) T4(-3.6,-6) T5(-2.8,-6) T6(-2,-6) T7(-1.2,-6) T8(-0.4,-6) T9(0.4,-6) T10(1.2,-6) T11(2,-6) T12(2.8,-6) T13(3.6,-6) T14(4.4,-6) T15(5.2,-6) T16(6,-6)
BGA1932_1MM_45X45MM
  round 0.483 smd: A2(-20.5,21.5) A3(-19.5,21.5) A4(-18.5,21.5) A5(-17.5,21.5) A6(-16.5,21.5) A7(-15.5,21.5) A8(-14.5,21.5) A9(-13.5,21.5) A10(-12.5,21.5) A11(-11.5,21.5) A12(-10.5,21.5) A13(-9.5,21.5) A14(-8.5,21.5) A15(-7.5,21.5) A16(-6.5,21.5) A17(-5.5,21.5) A18(-4.5,21.5) A19(-3.5,21.5) A20(-2.5,21.5) A21(-1.5,21.5) A22(-0.5,21.5) A23(0.5,21.5) A24(1.5,21.5) A25(2.5,21.5) A26(3.5,21.5) A27(4.5,21.5) A28(5.5,21.5) A29(6.5,21.5) A30(7.5,21.5) A31(8.5,21.5) A32(9.5,21.5) A33(10.5,21.5) A34(11.5,21.5) A35(12.5,21.5) A36(13.5,21.5) A37(14.5,21.5) A38(15.5,21.5) A39(16.5,21.5) A40(17.5,21.5) A41(18.5,21.5) A42(19.5,21.5) A43(20.5,21.5) AA1(-21.5,1.5) AA2(-20.5,1.5) AA3(-19.5,1.5) AA4(-18.5,1.5) AA5(-17.5,1.5) AA6(-16.5,1.5) AA7(-15.5,1.5) AA8(-14.5,1.5) AA9(-13.5,1.5) AA10(-12.5,1.5) AA11(-11.5,1.5) AA12(-10.5,1.5) AA13(-9.5,1.5) AA14(-8.5,1.5) AA15(-7.5,1.5) AA16(-6.5,1.5) AA17(-5.5,1.5) AA18(-4.5,1.5) AA19(-3.5,1.5) AA20(-2.5,1.5) AA21(-1.5,1.5) AA22(-0.5,1.5) AA23(0.5,1.5) AA24(1.5,1.5) AA25(2.5,1.5) AA26(3.5,1.5) AA27(4.5,1.5) AA28(5.5,1.5) AA29(6.5,1.5) AA30(7.5,1.5) AA31(8.5,1.5) AA32(9.5,1.5) AA33(10.5,1.5) AA34(11.5,1.5) AA35(12.5,1.5) AA36(13.5,1.5) AA37(14.5,1.5) AA38(15.5,1.5) AA39(16.5,1.5) AA40(17.5,1.5) AA41(18.5,1.5) AA42(19.5,1.5) AA43(20.5,1.5) AA44(21.5,1.5) AB1(-21.5,0.5) AB2(-20.5,0.5) AB3(-19.5,0.5) AB4(-18.5,0.5) AB5(-17.5,0.5) AB6(-16.5,0.5) AB7(-15.5,0.5) AB8(-14.5,0.5) AB9(-13.5,0.5) AB10(-12.5,0.5) AB11(-11.5,0.5) AB12(-10.5,0.5) AB13(-9.5,0.5) AB14(-8.5,0.5) AB15(-7.5,0.5) AB16(-6.5,0.5) AB17(-5.5,0.5) AB18(-4.5,0.5) AB19(-3.5,0.5) AB20(-2.5,0.5) AB21(-1.5,0.5) AB22(-0.5,0.5) AB23(0.5,0.5) AB24(1.5,0.5) AB25(2.5,0.5) AB26(3.5,0.5) AB27(4.5,0.5) AB28(5.5,0.5) AB29(6.5,0.5) AB30(7.5,0.5) AB31(8.5,0.5) AB32(9.5,0.5) AB33(10.5,0.5) AB34(11.5,0.5) AB35(12.5,0.5) AB36(13.5,0.5) AB37(14.5,0.5) AB38(15.5,0.5) AB39(16.5,0.5) AB40(17.5,0.5) AB41(18.5,0.5) AB42(19.5,0.5) AB43(20.5,0.5) AB44(21.5,0.5) AC1(-21.5,-0.5) AC2(-20.5,-0.5) AC3(-19.5,-0.5) AC4(-18.5,-0.5) AC5(-17.5,-0.5) AC6(-16.5,-0.5) AC7(-15.5,-0.5) AC8(-14.5,-0.5) AC9(-13.5,-0.5) AC10(-12.5,-0.5) AC11(-11.5,-0.5) AC12(-10.5,-0.5) AC13(-9.5,-0.5) AC14(-8.5,-0.5) AC15(-7.5,-0.5) AC16(-6.5,-0.5) AC17(-5.5,-0.5) AC18(-4.5,-0.5) AC19(-3.5,-0.5) AC20(-2.5,-0.5) AC21(-1.5,-0.5) AC22(-0.5,-0.5) AC23(0.5,-0.5) AC24(1.5,-0.5) AC25(2.5,-0.5) AC26(3.5,-0.5) AC27(4.5,-0.5) AC28(5.5,-0.5) AC29(6.5,-0.5) AC30(7.5,-0.5) AC31(8.5,-0.5) AC32(9.5,-0.5) AC33(10.5,-0.5) AC34(11.5,-0.5) AC35(12.5,-0.5) AC36(13.5,-0.5) AC37(14.5,-0.5) AC38(15.5,-0.5) AC39(16.5,-0.5) AC40(17.5,-0.5) AC41(18.5,-0.5) AC42(19.5,-0.5) AC43(20.5,-0.5) AC44(21.5,-0.5) AD1(-21.5,-1.5) AD2(-20.5,-1.5) AD3(-19.5,-1.5) AD4(-18.5,-1.5) AD5(-17.5,-1.5) AD6(-16.5,-1.5) AD7(-15.5,-1.5) AD8(-14.5,-1.5) AD9(-13.5,-1.5) AD10(-12.5,-1.5) AD11(-11.5,-1.5) AD12(-10.5,-1.5) AD13(-9.5,-1.5) AD14(-8.5,-1.5) AD15(-7.5,-1.5) AD16(-6.5,-1.5) AD17(-5.5,-1.5) AD18(-4.5,-1.5) AD19(-3.5,-1.5) AD20(-2.5,-1.5) AD21(-1.5,-1.5) AD22(-0.5,-1.5) AD23(0.5,-1.5) AD24(1.5,-1.5) AD25(2.5,-1.5) AD26(3.5,-1.5) AD27(4.5,-1.5) AD28(5.5,-1.5) AD29(6.5,-1.5) AD30(7.5,-1.5) AD31(8.5,-1.5) AD32(9.5,-1.5) AD33(10.5,-1.5) AD34(11.5,-1.5) AD35(12.5,-1.5) AD36(13.5,-1.5) AD37(14.5,-1.5) AD38(15.5,-1.5) AD39(16.5,-1.5) AD40(17.5,-1.5) AD41(18.5,-1.5) AD42(19.5,-1.5) AD43(20.5,-1.5) AD44(21.5,-1.5) AE1(-21.5,-2.5) AE2(-20.5,-2.5) AE3(-19.5,-2.5) AE4(-18.5,-2.5) AE5(-17.5,-2.5) AE6(-16.5,-2.5) AE7(-15.5,-2.5) AE8(-14.5,-2.5) AE9(-13.5,-2.5) AE10(-12.5,-2.5) AE11(-11.5,-2.5) AE12(-10.5,-2.5) AE13(-9.5,-2.5) AE14(-8.5,-2.5) AE15(-7.5,-2.5) AE16(-6.5,-2.5) AE17(-5.5,-2.5) AE18(-4.5,-2.5) AE19(-3.5,-2.5) AE20(-2.5,-2.5) AE21(-1.5,-2.5) AE22(-0.5,-2.5) AE23(0.5,-2.5) AE24(1.5,-2.5) AE25(2.5,-2.5) AE26(3.5,-2.5) AE27(4.5,-2.5) AE28(5.5,-2.5) AE29(6.5,-2.5) AE30(7.5,-2.5) AE31(8.5,-2.5) AE32(9.5,-2.5) AE33(10.5,-2.5) AE34(11.5,-2.5) AE35(12.5,-2.5) AE36(13.5,-2.5) AE37(14.5,-2.5) AE38(15.5,-2.5) AE39(16.5,-2.5) AE40(17.5,-2.5) AE41(18.5,-2.5) AE42(19.5,-2.5) AE43(20.5,-2.5) AE44(21.5,-2.5) AF1(-21.5,-3.5) AF2(-20.5,-3.5) AF3(-19.5,-3.5) AF4(-18.5,-3.5) AF5(-17.5,-3.5) AF6(-16.5,-3.5) AF7(-15.5,-3.5) AF8(-14.5,-3.5) AF9(-13.5,-3.5) AF10(-12.5,-3.5) AF11(-11.5,-3.5) AF12(-10.5,-3.5) AF13(-9.5,-3.5) AF14(-8.5,-3.5) AF15(-7.5,-3.5) AF16(-6.5,-3.5) AF17(-5.5,-3.5) AF18(-4.5,-3.5) AF19(-3.5,-3.5) AF20(-2.5,-3.5) AF21(-1.5,-3.5) AF22(-0.5,-3.5) AF23(0.5,-3.5) AF24(1.5,-3.5) AF25(2.5,-3.5) AF26(3.5,-3.5) AF27(4.5,-3.5) AF28(5.5,-3.5) AF29(6.5,-3.5) AF30(7.5,-3.5) AF31(8.5,-3.5) AF32(9.5,-3.5) AF33(10.5,-3.5) AF34(11.5,-3.5) AF35(12.5,-3.5) AF36(13.5,-3.5) AF37(14.5,-3.5) AF38(15.5,-3.5) AF39(16.5,-3.5) AF40(17.5,-3.5) AF41(18.5,-3.5) AF42(19.5,-3.5) AF43(20.5,-3.5) AF44(21.5,-3.5) AG1(-21.5,-4.5) AG2(-20.5,-4.5) AG3(-19.5,-4.5) AG4(-18.5,-4.5) AG5(-17.5,-4.5) AG6(-16.5,-4.5) AG7(-15.5,-4.5) AG8(-14.5,-4.5) AG9(-13.5,-4.5) AG10(-12.5,-4.5) AG11(-11.5,-4.5) AG12(-10.5,-4.5) AG13(-9.5,-4.5) AG14(-8.5,-4.5) AG15(-7.5,-4.5) AG16(-6.5,-4.5) AG17(-5.5,-4.5) AG18(-4.5,-4.5) AG19(-3.5,-4.5) AG20(-2.5,-4.5) AG21(-1.5,-4.5) AG22(-0.5,-4.5) AG23(0.5,-4.5) AG24(1.5,-4.5) AG25(2.5,-4.5) AG26(3.5,-4.5) AG27(4.5,-4.5) AG28(5.5,-4.5) AG29(6.5,-4.5) AG30(7.5,-4.5) AG31(8.5,-4.5) AG32(9.5,-4.5) AG33(10.5,-4.5) AG34(11.5,-4.5) AG35(12.5,-4.5) AG36(13.5,-4.5) AG37(14.5,-4.5) AG38(15.5,-4.5) AG39(16.5,-4.5) AG40(17.5,-4.5) AG41(18.5,-4.5) AG42(19.5,-4.5) AG43(20.5,-4.5) AG44(21.5,-4.5) AH1(-21.5,-5.5) AH2(-20.5,-5.5) AH3(-19.5,-5.5) AH4(-18.5,-5.5) AH5(-17.5,-5.5) AH6(-16.5,-5.5) AH7(-15.5,-5.5) AH8(-14.5,-5.5) AH9(-13.5,-5.5) AH10(-12.5,-5.5) AH11(-11.5,-5.5) AH12(-10.5,-5.5) AH13(-9.5,-5.5) AH14(-8.5,-5.5) AH15(-7.5,-5.5) AH16(-6.5,-5.5) AH17(-5.5,-5.5) AH18(-4.5,-5.5) AH19(-3.5,-5.5) AH20(-2.5,-5.5) AH21(-1.5,-5.5) AH22(-0.5,-5.5) AH23(0.5,-5.5) AH24(1.5,-5.5) AH25(2.5,-5.5) AH26(3.5,-5.5) AH27(4.5,-5.5) AH28(5.5,-5.5) AH29(6.5,-5.5) AH30(7.5,-5.5) AH31(8.5,-5.5) AH32(9.5,-5.5) AH33(10.5,-5.5) AH34(11.5,-5.5) AH35(12.5,-5.5) AH36(13.5,-5.5) AH37(14.5,-5.5) AH38(15.5,-5.5) AH39(16.5,-5.5) AH40(17.5,-5.5) AH41(18.5,-5.5) AH42(19.5,-5.5) AH43(20.5,-5.5) AH44(21.5,-5.5) AJ1(-21.5,-6.5) AJ2(-20.5,-6.5) AJ3(-19.5,-6.5) AJ4(-18.5,-6.5) AJ5(-17.5,-6.5) AJ6(-16.5,-6.5) AJ7(-15.5,-6.5) AJ8(-14.5,-6.5) AJ9(-13.5,-6.5) AJ10(-12.5,-6.5) AJ11(-11.5,-6.5) AJ12(-10.5,-6.5) AJ13(-9.5,-6.5) AJ14(-8.5,-6.5) AJ15(-7.5,-6.5) AJ16(-6.5,-6.5) AJ17(-5.5,-6.5) AJ18(-4.5,-6.5) AJ19(-3.5,-6.5) AJ20(-2.5,-6.5) AJ21(-1.5,-6.5) AJ22(-0.5,-6.5) AJ23(0.5,-6.5) AJ24(1.5,-6.5) AJ25(2.5,-6.5) AJ26(3.5,-6.5) AJ27(4.5,-6.5) AJ28(5.5,-6.5) AJ29(6.5,-6.5) AJ30(7.5,-6.5) AJ31(8.5,-6.5) AJ32(9.5,-6.5) AJ33(10.5,-6.5) AJ34(11.5,-6.5) AJ35(12.5,-6.5) AJ36(13.5,-6.5) AJ37(14.5,-6.5) AJ38(15.5,-6.5) AJ39(16.5,-6.5) AJ40(17.5,-6.5) AJ41(18.5,-6.5) AJ42(19.5,-6.5) AJ43(20.5,-6.5) AJ44(21.5,-6.5) AK1(-21.5,-7.5) AK2(-20.5,-7.5) AK3(-19.5,-7.5) AK4(-18.5,-7.5) AK5(-17.5,-7.5) AK6(-16.5,-7.5) AK7(-15.5,-7.5) AK8(-14.5,-7.5) AK9(-13.5,-7.5) AK10(-12.5,-7.5) AK11(-11.5,-7.5) AK12(-10.5,-7.5) AK13(-9.5,-7.5) AK14(-8.5,-7.5) AK15(-7.5,-7.5) AK16(-6.5,-7.5) AK17(-5.5,-7.5) AK18(-4.5,-7.5) AK19(-3.5,-7.5) AK20(-2.5,-7.5) AK21(-1.5,-7.5) AK22(-0.5,-7.5) AK23(0.5,-7.5) AK24(1.5,-7.5) AK25(2.5,-7.5) AK26(3.5,-7.5) AK27(4.5,-7.5) AK28(5.5,-7.5) AK29(6.5,-7.5) AK30(7.5,-7.5) AK31(8.5,-7.5) AK32(9.5,-7.5) AK33(10.5,-7.5) AK34(11.5,-7.5) AK35(12.5,-7.5) AK36(13.5,-7.5) AK37(14.5,-7.5) AK38(15.5,-7.5) AK39(16.5,-7.5) AK40(17.5,-7.5) AK41(18.5,-7.5) AK42(19.5,-7.5) AK43(20.5,-7.5) AK44(21.5,-7.5) AL1(-21.5,-8.5) AL2(-20.5,-8.5) AL3(-19.5,-8.5) AL4(-18.5,-8.5) AL5(-17.5,-8.5) AL6(-16.5,-8.5) AL7(-15.5,-8.5) AL8(-14.5,-8.5) AL9(-13.5,-8.5) AL10(-12.5,-8.5) AL11(-11.5,-8.5) AL12(-10.5,-8.5) AL13(-9.5,-8.5) AL14(-8.5,-8.5) AL15(-7.5,-8.5) AL16(-6.5,-8.5) AL17(-5.5,-8.5) AL18(-4.5,-8.5) AL19(-3.5,-8.5) AL20(-2.5,-8.5) AL21(-1.5,-8.5) AL22(-0.5,-8.5) AL23(0.5,-8.5) AL24(1.5,-8.5) AL25(2.5,-8.5) AL26(3.5,-8.5) AL27(4.5,-8.5) AL28(5.5,-8.5) AL29(6.5,-8.5) AL30(7.5,-8.5) AL31(8.5,-8.5) AL32(9.5,-8.5) AL33(10.5,-8.5) AL34(11.5,-8.5) AL35(12.5,-8.5) AL36(13.5,-8.5) AL37(14.5,-8.5) AL38(15.5,-8.5) AL39(16.5,-8.5) AL40(17.5,-8.5) AL41(18.5,-8.5) AL42(19.5,-8.5) AL43(20.5,-8.5) AL44(21.5,-8.5) AM1(-21.5,-9.5) AM2(-20.5,-9.5) AM3(-19.5,-9.5) AM4(-18.5,-9.5) AM5(-17.5,-9.5) AM6(-16.5,-9.5) AM7(-15.5,-9.5) AM8(-14.5,-9.5) AM9(-13.5,-9.5) AM10(-12.5,-9.5) AM11(-11.5,-9.5) AM12(-10.5,-9.5) AM13(-9.5,-9.5) AM14(-8.5,-9.5) AM15(-7.5,-9.5) AM16(-6.5,-9.5) AM17(-5.5,-9.5) AM18(-4.5,-9.5) AM19(-3.5,-9.5) AM20(-2.5,-9.5) AM21(-1.5,-9.5) AM22(-0.5,-9.5) AM23(0.5,-9.5) AM24(1.5,-9.5) AM25(2.5,-9.5) AM26(3.5,-9.5) AM27(4.5,-9.5) AM28(5.5,-9.5) AM29(6.5,-9.5) AM30(7.5,-9.5) AM31(8.5,-9.5) AM32(9.5,-9.5) AM33(10.5,-9.5) AM34(11.5,-9.5) AM35(12.5,-9.5) AM36(13.5,-9.5) AM37(14.5,-9.5) AM38(15.5,-9.5) AM39(16.5,-9.5) AM40(17.5,-9.5) AM41(18.5,-9.5) AM42(19.5,-9.5) AM43(20.5,-9.5) AM44(21.5,-9.5) AN1(-21.5,-10.5) AN2(-20.5,-10.5) AN3(-19.5,-10.5) AN4(-18.5,-10.5) AN5(-17.5,-10.5) AN6(-16.5,-10.5) AN7(-15.5,-10.5) AN8(-14.5,-10.5) AN9(-13.5,-10.5) AN10(-12.5,-10.5) AN11(-11.5,-10.5) AN12(-10.5,-10.5) AN13(-9.5,-10.5) AN14(-8.5,-10.5) AN15(-7.5,-10.5) AN16(-6.5,-10.5) AN17(-5.5,-10.5) AN18(-4.5,-10.5) AN19(-3.5,-10.5) AN20(-2.5,-10.5) AN21(-1.5,-10.5) AN22(-0.5,-10.5) AN23(0.5,-10.5) AN24(1.5,-10.5) AN25(2.5,-10.5) AN26(3.5,-10.5) AN27(4.5,-10.5) AN28(5.5,-10.5) AN29(6.5,-10.5) AN30(7.5,-10.5) AN31(8.5,-10.5) AN32(9.5,-10.5) AN33(10.5,-10.5) AN34(11.5,-10.5) AN35(12.5,-10.5) AN36(13.5,-10.5) AN37(14.5,-10.5) AN38(15.5,-10.5) AN39(16.5,-10.5) AN40(17.5,-10.5) AN41(18.5,-10.5) AN42(19.5,-10.5) AN43(20.5,-10.5) AN44(21.5,-10.5) AP1(-21.5,-11.5) AP2(-20.5,-11.5) AP3(-19.5,-11.5) AP4(-18.5,-11.5) AP5(-17.5,-11.5) AP6(-16.5,-11.5) AP7(-15.5,-11.5) AP8(-14.5,-11.5) AP9(-13.5,-11.5) AP10(-12.5,-11.5) AP11(-11.5,-11.5) AP12(-10.5,-11.5) AP13(-9.5,-11.5) AP14(-8.5,-11.5) AP15(-7.5,-11.5) AP16(-6.5,-11.5) AP17(-5.5,-11.5) AP18(-4.5,-11.5) AP19(-3.5,-11.5) AP20(-2.5,-11.5) AP21(-1.5,-11.5) AP22(-0.5,-11.5) AP23(0.5,-11.5) AP24(1.5,-11.5) AP25(2.5,-11.5) AP26(3.5,-11.5) AP27(4.5,-11.5) AP28(5.5,-11.5) AP29(6.5,-11.5) AP30(7.5,-11.5) AP31(8.5,-11.5) AP32(9.5,-11.5) AP33(10.5,-11.5) AP34(11.5,-11.5) AP35(12.5,-11.5) AP36(13.5,-11.5) AP37(14.5,-11.5) AP38(15.5,-11.5) AP39(16.5,-11.5) AP40(17.5,-11.5) AP41(18.5,-11.5) AP42(19.5,-11.5) AP43(20.5,-11.5) AP44(21.5,-11.5) AR1(-21.5,-12.5) AR2(-20.5,-12.5) AR3(-19.5,-12.5) AR4(-18.5,-12.5) AR5(-17.5,-12.5) AR6(-16.5,-12.5) AR7(-15.5,-12.5) AR8(-14.5,-12.5) AR9(-13.5,-12.5) AR10(-12.5,-12.5) AR11(-11.5,-12.5) AR12(-10.5,-12.5) AR13(-9.5,-12.5) AR14(-8.5,-12.5) AR15(-7.5,-12.5) AR16(-6.5,-12.5) AR17(-5.5,-12.5) AR18(-4.5,-12.5) AR19(-3.5,-12.5) AR20(-2.5,-12.5) AR21(-1.5,-12.5) AR22(-0.5,-12.5) AR23(0.5,-12.5) AR24(1.5,-12.5) AR25(2.5,-12.5) AR26(3.5,-12.5) AR27(4.5,-12.5) AR28(5.5,-12.5) AR29(6.5,-12.5) AR30(7.5,-12.5) AR31(8.5,-12.5) AR32(9.5,-12.5) AR33(10.5,-12.5) AR34(11.5,-12.5) AR35(12.5,-12.5) AR36(13.5,-12.5) AR37(14.5,-12.5) AR38(15.5,-12.5) AR39(16.5,-12.5) AR40(17.5,-12.5) AR41(18.5,-12.5) AR42(19.5,-12.5) AR43(20.5,-12.5) AR44(21.5,-12.5) AT1(-21.5,-13.5) AT2(-20.5,-13.5) AT3(-19.5,-13.5) AT4(-18.5,-13.5) AT5(-17.5,-13.5) AT6(-16.5,-13.5) AT7(-15.5,-13.5) AT8(-14.5,-13.5) AT9(-13.5,-13.5) AT10(-12.5,-13.5) AT11(-11.5,-13.5) AT12(-10.5,-13.5) AT13(-9.5,-13.5) AT14(-8.5,-13.5) AT15(-7.5,-13.5) AT16(-6.5,-13.5) AT17(-5.5,-13.5) AT18(-4.5,-13.5) AT19(-3.5,-13.5) AT20(-2.5,-13.5) AT21(-1.5,-13.5) AT22(-0.5,-13.5) AT23(0.5,-13.5) AT24(1.5,-13.5) AT25(2.5,-13.5) AT26(3.5,-13.5) AT27(4.5,-13.5) AT28(5.5,-13.5) AT29(6.5,-13.5) AT30(7.5,-13.5) AT31(8.5,-13.5) AT32(9.5,-13.5) AT33(10.5,-13.5) AT34(11.5,-13.5) AT35(12.5,-13.5) AT36(13.5,-13.5) AT37(14.5,-13.5) AT38(15.5,-13.5) AT39(16.5,-13.5) AT40(17.5,-13.5) AT41(18.5,-13.5) AT42(19.5,-13.5) AT43(20.5,-13.5) AT44(21.5,-13.5) AU1(-21.5,-14.5) AU2(-20.5,-14.5) AU3(-19.5,-14.5) AU4(-18.5,-14.5) AU5(-17.5,-14.5) AU6(-16.5,-14.5) AU7(-15.5,-14.5) AU8(-14.5,-14.5) AU9(-13.5,-14.5) AU10(-12.5,-14.5) AU11(-11.5,-14.5) AU12(-10.5,-14.5) AU13(-9.5,-14.5) AU14(-8.5,-14.5) AU15(-7.5,-14.5) AU16(-6.5,-14.5) AU17(-5.5,-14.5) AU18(-4.5,-14.5) AU19(-3.5,-14.5) AU20(-2.5,-14.5) AU21(-1.5,-14.5) AU22(-0.5,-14.5) AU23(0.5,-14.5) AU24(1.5,-14.5) AU25(2.5,-14.5) AU26(3.5,-14.5) AU27(4.5,-14.5) AU28(5.5,-14.5) AU29(6.5,-14.5) AU30(7.5,-14.5) AU31(8.5,-14.5) AU32(9.5,-14.5) AU33(10.5,-14.5) AU34(11.5,-14.5) AU35(12.5,-14.5) AU36(13.5,-14.5) AU37(14.5,-14.5) AU38(15.5,-14.5) AU39(16.5,-14.5) AU40(17.5,-14.5) AU41(18.5,-14.5) AU42(19.5,-14.5) AU43(20.5,-14.5) AU44(21.5,-14.5) AV1(-21.5,-15.5) AV2(-20.5,-15.5) AV3(-19.5,-15.5) AV4(-18.5,-15.5) AV5(-17.5,-15.5) AV6(-16.5,-15.5) AV7(-15.5,-15.5) AV8(-14.5,-15.5) AV9(-13.5,-15.5) AV10(-12.5,-15.5) AV11(-11.5,-15.5) AV12(-10.5,-15.5) AV13(-9.5,-15.5) AV14(-8.5,-15.5) AV15(-7.5,-15.5) AV16(-6.5,-15.5) AV17(-5.5,-15.5) AV18(-4.5,-15.5) AV19(-3.5,-15.5) AV20(-2.5,-15.5) AV21(-1.5,-15.5) AV22(-0.5,-15.5) AV23(0.5,-15.5) AV24(1.5,-15.5) AV25(2.5,-15.5) AV26(3.5,-15.5) AV27(4.5,-15.5) AV28(5.5,-15.5) AV29(6.5,-15.5) AV30(7.5,-15.5) AV31(8.5,-15.5) AV32(9.5,-15.5) AV33(10.5,-15.5) AV34(11.5,-15.5) AV35(12.5,-15.5) AV36(13.5,-15.5) AV37(14.5,-15.5) AV38(15.5,-15.5) AV39(16.5,-15.5) AV40(17.5,-15.5) AV41(18.5,-15.5) AV42(19.5,-15.5) AV43(20.5,-15.5) AV44(21.5,-15.5) AW1(-21.5,-16.5) AW2(-20.5,-16.5) AW3(-19.5,-16.5) AW4(-18.5,-16.5) AW5(-17.5,-16.5) AW6(-16.5,-16.5) AW7(-15.5,-16.5) AW8(-14.5,-16.5) AW9(-13.5,-16.5) AW10(-12.5,-16.5) AW11(-11.5,-16.5) AW12(-10.5,-16.5) AW13(-9.5,-16.5) AW14(-8.5,-16.5) AW15(-7.5,-16.5) AW16(-6.5,-16.5) AW17(-5.5,-16.5) AW18(-4.5,-16.5) AW19(-3.5,-16.5) AW20(-2.5,-16.5) AW21(-1.5,-16.5) AW22(-0.5,-16.5) AW23(0.5,-16.5) AW24(1.5,-16.5) AW25(2.5,-16.5) AW26(3.5,-16.5) AW27(4.5,-16.5) AW28(5.5,-16.5) AW29(6.5,-16.5) AW30(7.5,-16.5) AW31(8.5,-16.5) AW32(9.5,-16.5) AW33(10.5,-16.5) AW34(11.5,-16.5) AW35(12.5,-16.5) AW36(13.5,-16.5) AW37(14.5,-16.5) AW38(15.5,-16.5) AW39(16.5,-16.5) AW40(17.5,-16.5) AW41(18.5,-16.5) AW42(19.5,-16.5) AW43(20.5,-16.5) AW44(21.5,-16.5) AY1(-21.5,-17.5) AY2(-20.5,-17.5) AY3(-19.5,-17.5) AY4(-18.5,-17.5) AY5(-17.5,-17.5) AY6(-16.5,-17.5) AY7(-15.5,-17.5) AY8(-14.5,-17.5) AY9(-13.5,-17.5) AY10(-12.5,-17.5) AY11(-11.5,-17.5) AY12(-10.5,-17.5) AY13(-9.5,-17.5) AY14(-8.5,-17.5) AY15(-7.5,-17.5) AY16(-6.5,-17.5) AY17(-5.5,-17.5) AY18(-4.5,-17.5) AY19(-3.5,-17.5) AY20(-2.5,-17.5) AY21(-1.5,-17.5) AY22(-0.5,-17.5) AY23(0.5,-17.5) AY24(1.5,-17.5) AY25(2.5,-17.5) AY26(3.5,-17.5) AY27(4.5,-17.5) AY28(5.5,-17.5) AY29(6.5,-17.5) AY30(7.5,-17.5) AY31(8.5,-17.5) AY32(9.5,-17.5) AY33(10.5,-17.5) AY34(11.5,-17.5) AY35(12.5,-17.5) AY36(13.5,-17.5) AY37(14.5,-17.5) AY38(15.5,-17.5) AY39(16.5,-17.5) AY40(17.5,-17.5) AY41(18.5,-17.5) AY42(19.5,-17.5) AY43(20.5,-17.5) AY44(21.5,-17.5) B1(-21.5,20.5) B2(-20.5,20.5) B3(-19.5,20.5) B4(-18.5,20.5) B5(-17.5,20.5) B6(-16.5,20.5) B7(-15.5,20.5) B8(-14.5,20.5) B9(-13.5,20.5) B10(-12.5,20.5) B11(-11.5,20.5) B12(-10.5,20.5) B13(-9.5,20.5) B14(-8.5,20.5) B15(-7.5,20.5) B16(-6.5,20.5) B17(-5.5,20.5) B18(-4.5,20.5) B19(-3.5,20.5) B20(-2.5,20.5) B21(-1.5,20.5) B22(-0.5,20.5) B23(0.5,20.5) B24(1.5,20.5) B25(2.5,20.5) B26(3.5,20.5) B27(4.5,20.5) B28(5.5,20.5) B29(6.5,20.5) B30(7.5,20.5) B31(8.5,20.5) B32(9.5,20.5) B33(10.5,20.5) B34(11.5,20.5) B35(12.5,20.5) B36(13.5,20.5) B37(14.5,20.5) B38(15.5,20.5) B39(16.5,20.5) B40(17.5,20.5) B41(18.5,20.5) B42(19.5,20.5) B43(20.5,20.5) B44(21.5,20.5) BA1(-21.5,-18.5) BA2(-20.5,-18.5) BA3(-19.5,-18.5) BA4(-18.5,-18.5) BA5(-17.5,-18.5) BA6(-16.5,-18.5) BA7(-15.5,-18.5) BA8(-14.5,-18.5) BA9(-13.5,-18.5) BA10(-12.5,-18.5) BA11(-11.5,-18.5) BA12(-10.5,-18.5) BA13(-9.5,-18.5) BA14(-8.5,-18.5) BA15(-7.5,-18.5) BA16(-6.5,-18.5) BA17(-5.5,-18.5) BA18(-4.5,-18.5) BA19(-3.5,-18.5) BA20(-2.5,-18.5) BA21(-1.5,-18.5) BA22(-0.5,-18.5) BA23(0.5,-18.5) BA24(1.5,-18.5) BA25(2.5,-18.5) BA26(3.5,-18.5) BA27(4.5,-18.5) BA28(5.5,-18.5) BA29(6.5,-18.5) BA30(7.5,-18.5) BA31(8.5,-18.5) BA32(9.5,-18.5) BA33(10.5,-18.5) BA34(11.5,-18.5) BA35(12.5,-18.5) BA36(13.5,-18.5) BA37(14.5,-18.5) BA38(15.5,-18.5) BA39(16.5,-18.5) BA40(17.5,-18.5) BA41(18.5,-18.5) BA42(19.5,-18.5) BA43(20.5,-18.5) BA44(21.5,-18.5) BB1(-21.5,-19.5) BB2(-20.5,-19.5) BB3(-19.5,-19.5) BB4(-18.5,-19.5) BB5(-17.5,-19.5) BB6(-16.5,-19.5) BB7(-15.5,-19.5) BB8(-14.5,-19.5) BB9(-13.5,-19.5) BB10(-12.5,-19.5) BB11(-11.5,-19.5) BB12(-10.5,-19.5) BB13(-9.5,-19.5) BB14(-8.5,-19.5) BB15(-7.5,-19.5) BB16(-6.5,-19.5) BB17(-5.5,-19.5) BB18(-4.5,-19.5) BB19(-3.5,-19.5) BB20(-2.5,-19.5) BB21(-1.5,-19.5) BB22(-0.5,-19.5) BB23(0.5,-19.5) BB24(1.5,-19.5) BB25(2.5,-19.5) BB26(3.5,-19.5) BB27(4.5,-19.5) BB28(5.5,-19.5) BB29(6.5,-19.5) BB30(7.5,-19.5) BB31(8.5,-19.5) BB32(9.5,-19.5) BB33(10.5,-19.5) BB34(11.5,-19.5) BB35(12.5,-19.5) BB36(13.5,-19.5) BB37(14.5,-19.5) BB38(15.5,-19.5) BB39(16.5,-19.5) BB40(17.5,-19.5) BB41(18.5,-19.5) BB42(19.5,-19.5) BB43(20.5,-19.5) BB44(21.5,-19.5) BC1(-21.5,-20.5) BC2(-20.5,-20.5) BC3(-19.5,-20.5) BC4(-18.5,-20.5) BC5(-17.5,-20.5) BC6(-16.5,-20.5) BC7(-15.5,-20.5) BC8(-14.5,-20.5) BC9(-13.5,-20.5) BC10(-12.5,-20.5) BC11(-11.5,-20.5) BC12(-10.5,-20.5) BC13(-9.5,-20.5) BC14(-8.5,-20.5) BC15(-7.5,-20.5) BC16(-6.5,-20.5) BC17(-5.5,-20.5) BC18(-4.5,-20.5) BC19(-3.5,-20.5) BC20(-2.5,-20.5) BC21(-1.5,-20.5) BC22(-0.5,-20.5) BC23(0.5,-20.5) BC24(1.5,-20.5) BC25(2.5,-20.5) BC26(3.5,-20.5) BC27(4.5,-20.5) BC28(5.5,-20.5) BC29(6.5,-20.5) BC30(7.5,-20.5) BC31(8.5,-20.5) BC32(9.5,-20.5) BC33(10.5,-20.5) BC34(11.5,-20.5) BC35(12.5,-20.5) BC36(13.5,-20.5) BC37(14.5,-20.5) BC38(15.5,-20.5) BC39(16.5,-20.5) BC40(17.5,-20.5) BC41(18.5,-20.5) BC42(19.5,-20.5) BC43(20.5,-20.5) BC44(21.5,-20.5) BD2(-20.5,-21.5) BD3(-19.5,-21.5) BD4(-18.5,-21.5) BD5(-17.5,-21.5) BD6(-16.5,-21.5) BD7(-15.5,-21.5) BD8(-14.5,-21.5) BD9(-13.5,-21.5) BD10(-12.5,-21.5) BD11(-11.5,-21.5) BD12(-10.5,-21.5) BD13(-9.5,-21.5) BD14(-8.5,-21.5) BD15(-7.5,-21.5) BD16(-6.5,-21.5) BD17(-5.5,-21.5) BD18(-4.5,-21.5) BD19(-3.5,-21.5) BD20(-2.5,-21.5) BD21(-1.5,-21.5) BD22(-0.5,-21.5) BD23(0.5,-21.5) BD24(1.5,-21.5) BD25(2.5,-21.5) BD26(3.5,-21.5) BD27(4.5,-21.5) BD28(5.5,-21.5) BD29(6.5,-21.5) BD30(7.5,-21.5) BD31(8.5,-21.5) BD32(9.5,-21.5) BD33(10.5,-21.5) BD34(11.5,-21.5) BD35(12.5,-21.5) BD36(13.5,-21.5) BD37(14.5,-21.5) BD38(15.5,-21.5) BD39(16.5,-21.5) BD40(17.5,-21.5) BD41(18.5,-21.5) BD42(19.5,-21.5) BD43(20.5,-21.5) C1(-21.5,19.5) C2(-20.5,19.5) C3(-19.5,19.5) C4(-18.5,19.5) C5(-17.5,19.5) C6(-16.5,19.5) C7(-15.5,19.5) C8(-14.5,19.5) C9(-13.5,19.5) C10(-12.5,19.5) C11(-11.5,19.5) C12(-10.5,19.5) C13(-9.5,19.5) C14(-8.5,19.5) C15(-7.5,19.5) C16(-6.5,19.5) C17(-5.5,19.5) C18(-4.5,19.5) C19(-3.5,19.5) C20(-2.5,19.5) C21(-1.5,19.5) C22(-0.5,19.5) C23(0.5,19.5) C24(1.5,19.5) C25(2.5,19.5) C26(3.5,19.5) C27(4.5,19.5) C28(5.5,19.5) C29(6.5,19.5) C30(7.5,19.5) C31(8.5,19.5) C32(9.5,19.5) C33(10.5,19.5) C34(11.5,19.5) C35(12.5,19.5) C36(13.5,19.5) C37(14.5,19.5) C38(15.5,19.5) C39(16.5,19.5) C40(17.5,19.5) C41(18.5,19.5) C42(19.5,19.5) C43(20.5,19.5) C44(21.5,19.5) D1(-21.5,18.5) D2(-20.5,18.5) D3(-19.5,18.5) D4(-18.5,18.5) D5(-17.5,18.5) D6(-16.5,18.5) D7(-15.5,18.5) D8(-14.5,18.5) D9(-13.5,18.5) D10(-12.5,18.5) D11(-11.5,18.5) D12(-10.5,18.5) D13(-9.5,18.5) D14(-8.5,18.5) D15(-7.5,18.5) D16(-6.5,18.5) D17(-5.5,18.5) D18(-4.5,18.5) D19(-3.5,18.5) D20(-2.5,18.5) D21(-1.5,18.5) D22(-0.5,18.5) D23(0.5,18.5) D24(1.5,18.5) D25(2.5,18.5) D26(3.5,18.5) D27(4.5,18.5) D28(5.5,18.5) D29(6.5,18.5) D30(7.5,18.5) D31(8.5,18.5) D32(9.5,18.5) D33(10.5,18.5) D34(11.5,18.5) D35(12.5,18.5) D36(13.5,18.5) D37(14.5,18.5) D38(15.5,18.5) D39(16.5,18.5) D40(17.5,18.5) D41(18.5,18.5) D42(19.5,18.5) D43(20.5,18.5) D44(21.5,18.5) E1(-21.5,17.5) E2(-20.5,17.5) E3(-19.5,17.5) E4(-18.5,17.5) E5(-17.5,17.5) E6(-16.5,17.5) E7(-15.5,17.5) E8(-14.5,17.5) E9(-13.5,17.5) E10(-12.5,17.5) E11(-11.5,17.5) E12(-10.5,17.5) E13(-9.5,17.5) E14(-8.5,17.5) E15(-7.5,17.5) E16(-6.5,17.5) E17(-5.5,17.5) E18(-4.5,17.5) E19(-3.5,17.5) E20(-2.5,17.5) E21(-1.5,17.5) E22(-0.5,17.5) E23(0.5,17.5) E24(1.5,17.5) E25(2.5,17.5) E26(3.5,17.5) E27(4.5,17.5) E28(5.5,17.5) E29(6.5,17.5) E30(7.5,17.5) E31(8.5,17.5) E32(9.5,17.5) E33(10.5,17.5) E34(11.5,17.5) E35(12.5,17.5) E36(13.5,17.5) E37(14.5,17.5) E38(15.5,17.5) E39(16.5,17.5) E40(17.5,17.5) E41(18.5,17.5) E42(19.5,17.5) E43(20.5,17.5) E44(21.5,17.5) F1(-21.5,16.5) F2(-20.5,16.5) F3(-19.5,16.5) F4(-18.5,16.5) F5(-17.5,16.5) F6(-16.5,16.5) F7(-15.5,16.5) F8(-14.5,16.5) F9(-13.5,16.5) F10(-12.5,16.5) F11(-11.5,16.5) F12(-10.5,16.5) F13(-9.5,16.5) F14(-8.5,16.5) F15(-7.5,16.5) F16(-6.5,16.5) F17(-5.5,16.5) F18(-4.5,16.5) F19(-3.5,16.5) F20(-2.5,16.5) F21(-1.5,16.5) F22(-0.5,16.5) F23(0.5,16.5) F24(1.5,16.5) F25(2.5,16.5) F26(3.5,16.5) F27(4.5,16.5) F28(5.5,16.5) F29(6.5,16.5) F30(7.5,16.5) F31(8.5,16.5) F32(9.5,16.5) F33(10.5,16.5) F34(11.5,16.5) F35(12.5,16.5) F36(13.5,16.5) F37(14.5,16.5) F38(15.5,16.5) F39(16.5,16.5) F40(17.5,16.5) F41(18.5,16.5) F42(19.5,16.5) F43(20.5,16.5) F44(21.5,16.5) G1(-21.5,15.5) G2(-20.5,15.5) G3(-19.5,15.5) G4(-18.5,15.5) G5(-17.5,15.5) G6(-16.5,15.5) G7(-15.5,15.5) G8(-14.5,15.5) G9(-13.5,15.5) G10(-12.5,15.5) G11(-11.5,15.5) G12(-10.5,15.5) G13(-9.5,15.5) G14(-8.5,15.5) G15(-7.5,15.5) G16(-6.5,15.5) G17(-5.5,15.5) G18(-4.5,15.5) G19(-3.5,15.5) G20(-2.5,15.5) G21(-1.5,15.5) G22(-0.5,15.5) G23(0.5,15.5) G24(1.5,15.5) G25(2.5,15.5) G26(3.5,15.5) G27(4.5,15.5) G28(5.5,15.5) G29(6.5,15.5) G30(7.5,15.5) G31(8.5,15.5) G32(9.5,15.5) G33(10.5,15.5) G34(11.5,15.5) G35(12.5,15.5) G36(13.5,15.5) G37(14.5,15.5) G38(15.5,15.5) G39(16.5,15.5) G40(17.5,15.5) G41(18.5,15.5) G42(19.5,15.5) G43(20.5,15.5) G44(21.5,15.5) H1(-21.5,14.5) H2(-20.5,14.5) H3(-19.5,14.5) H4(-18.5,14.5) H5(-17.5,14.5) H6(-16.5,14.5) H7(-15.5,14.5) H8(-14.5,14.5) H9(-13.5,14.5) H10(-12.5,14.5) H11(-11.5,14.5) H12(-10.5,14.5) H13(-9.5,14.5) H14(-8.5,14.5) H15(-7.5,14.5) H16(-6.5,14.5) H17(-5.5,14.5) H18(-4.5,14.5) H19(-3.5,14.5) H20(-2.5,14.5) H21(-1.5,14.5) H22(-0.5,14.5) H23(0.5,14.5) H24(1.5,14.5) H25(2.5,14.5) H26(3.5,14.5) H27(4.5,14.5) H28(5.5,14.5) H29(6.5,14.5) H30(7.5,14.5) H31(8.5,14.5) H32(9.5,14.5) H33(10.5,14.5) H34(11.5,14.5) H35(12.5,14.5) H36(13.5,14.5) H37(14.5,14.5) H38(15.5,14.5) H39(16.5,14.5) H40(17.5,14.5) H41(18.5,14.5) H42(19.5,14.5) H43(20.5,14.5) H44(21.5,14.5) J1(-21.5,13.5) J2(-20.5,13.5) J3(-19.5,13.5) J4(-18.5,13.5) J5(-17.5,13.5) J6(-16.5,13.5) J7(-15.5,13.5) J8(-14.5,13.5) J9(-13.5,13.5) J10(-12.5,13.5) J11(-11.5,13.5) J12(-10.5,13.5) J13(-9.5,13.5) J14(-8.5,13.5) J15(-7.5,13.5) J16(-6.5,13.5) J17(-5.5,13.5) J18(-4.5,13.5) J19(-3.5,13.5) J20(-2.5,13.5) J21(-1.5,13.5) J22(-0.5,13.5) J23(0.5,13.5) J24(1.5,13.5) J25(2.5,13.5) J26(3.5,13.5) J27(4.5,13.5) J28(5.5,13.5) J29(6.5,13.5) J30(7.5,13.5) J31(8.5,13.5) J32(9.5,13.5) J33(10.5,13.5) J34(11.5,13.5) J35(12.5,13.5) J36(13.5,13.5) J37(14.5,13.5) J38(15.5,13.5) J39(16.5,13.5) J40(17.5,13.5) J41(18.5,13.5) J42(19.5,13.5) J43(20.5,13.5) J44(21.5,13.5) K1(-21.5,12.5) K2(-20.5,12.5) K3(-19.5,12.5) K4(-18.5,12.5) K5(-17.5,12.5) K6(-16.5,12.5) K7(-15.5,12.5) K8(-14.5,12.5) K9(-13.5,12.5) K10(-12.5,12.5) K11(-11.5,12.5) K12(-10.5,12.5) K13(-9.5,12.5) K14(-8.5,12.5) K15(-7.5,12.5) K16(-6.5,12.5) K17(-5.5,12.5) K18(-4.5,12.5) K19(-3.5,12.5) K20(-2.5,12.5) K21(-1.5,12.5) K22(-0.5,12.5) K23(0.5,12.5) K24(1.5,12.5) K25(2.5,12.5) K26(3.5,12.5) K27(4.5,12.5) K28(5.5,12.5) K29(6.5,12.5) K30(7.5,12.5) K31(8.5,12.5) K32(9.5,12.5) K33(10.5,12.5) K34(11.5,12.5) K35(12.5,12.5) K36(13.5,12.5) K37(14.5,12.5) K38(15.5,12.5) K39(16.5,12.5) K40(17.5,12.5) K41(18.5,12.5) K42(19.5,12.5) K43(20.5,12.5) K44(21.5,12.5) L1(-21.5,11.5) L2(-20.5,11.5) L3(-19.5,11.5) L4(-18.5,11.5) L5(-17.5,11.5) L6(-16.5,11.5) L7(-15.5,11.5) L8(-14.5,11.5) L9(-13.5,11.5) L10(-12.5,11.5) L11(-11.5,11.5) L12(-10.5,11.5) L13(-9.5,11.5) L14(-8.5,11.5) L15(-7.5,11.5) L16(-6.5,11.5) L17(-5.5,11.5) L18(-4.5,11.5) L19(-3.5,11.5) L20(-2.5,11.5) L21(-1.5,11.5) L22(-0.5,11.5) L23(0.5,11.5) L24(1.5,11.5) L25(2.5,11.5) L26(3.5,11.5) L27(4.5,11.5) L28(5.5,11.5) L29(6.5,11.5) L30(7.5,11.5) L31(8.5,11.5) L32(9.5,11.5) L33(10.5,11.5) L34(11.5,11.5) L35(12.5,11.5) L36(13.5,11.5) L37(14.5,11.5) L38(15.5,11.5) L39(16.5,11.5) L40(17.5,11.5) L41(18.5,11.5) L42(19.5,11.5) L43(20.5,11.5) L44(21.5,11.5) M1(-21.5,10.5) M2(-20.5,10.5) M3(-19.5,10.5) M4(-18.5,10.5) M5(-17.5,10.5) M6(-16.5,10.5) M7(-15.5,10.5) M8(-14.5,10.5) M9(-13.5,10.5) M10(-12.5,10.5) M11(-11.5,10.5) M12(-10.5,10.5) M13(-9.5,10.5) M14(-8.5,10.5) M15(-7.5,10.5) M16(-6.5,10.5) M17(-5.5,10.5) M18(-4.5,10.5) M19(-3.5,10.5) M20(-2.5,10.5) M21(-1.5,10.5) M22(-0.5,10.5) M23(0.5,10.5) M24(1.5,10.5) M25(2.5,10.5) M26(3.5,10.5) M27(4.5,10.5) M28(5.5,10.5) M29(6.5,10.5) M30(7.5,10.5) M31(8.5,10.5) M32(9.5,10.5) M33(10.5,10.5) M34(11.5,10.5) M35(12.5,10.5) M36(13.5,10.5) M37(14.5,10.5) M38(15.5,10.5) M39(16.5,10.5) M40(17.5,10.5) M41(18.5,10.5) M42(19.5,10.5) M43(20.5,10.5) M44(21.5,10.5) N1(-21.5,9.5) N2(-20.5,9.5) N3(-19.5,9.5) N4(-18.5,9.5) N5(-17.5,9.5) N6(-16.5,9.5) N7(-15.5,9.5) N8(-14.5,9.5) N9(-13.5,9.5) N10(-12.5,9.5) N11(-11.5,9.5) N12(-10.5,9.5) N13(-9.5,9.5) N14(-8.5,9.5) N15(-7.5,9.5) N16(-6.5,9.5) N17(-5.5,9.5) N18(-4.5,9.5) N19(-3.5,9.5) N20(-2.5,9.5) N21(-1.5,9.5) N22(-0.5,9.5) N23(0.5,9.5) N24(1.5,9.5) N25(2.5,9.5) N26(3.5,9.5) N27(4.5,9.5) N28(5.5,9.5) N29(6.5,9.5) N30(7.5,9.5) N31(8.5,9.5) N32(9.5,9.5) N33(10.5,9.5) N34(11.5,9.5) N35(12.5,9.5) N36(13.5,9.5) N37(14.5,9.5) N38(15.5,9.5) N39(16.5,9.5) N40(17.5,9.5) N41(18.5,9.5) N42(19.5,9.5) N43(20.5,9.5) N44(21.5,9.5) P1(-21.5,8.5) P2(-20.5,8.5) P3(-19.5,8.5) P4(-18.5,8.5) P5(-17.5,8.5) P6(-16.5,8.5) P7(-15.5,8.5) P8(-14.5,8.5) P9(-13.5,8.5) P10(-12.5,8.5) P11(-11.5,8.5) P12(-10.5,8.5) P13(-9.5,8.5) P14(-8.5,8.5) P15(-7.5,8.5) P16(-6.5,8.5) P17(-5.5,8.5) P18(-4.5,8.5) P19(-3.5,8.5) P20(-2.5,8.5) P21(-1.5,8.5) P22(-0.5,8.5) P23(0.5,8.5) P24(1.5,8.5) P25(2.5,8.5) P26(3.5,8.5) P27(4.5,8.5) P28(5.5,8.5) P29(6.5,8.5) P30(7.5,8.5) P31(8.5,8.5) P32(9.5,8.5) P33(10.5,8.5) P34(11.5,8.5) P35(12.5,8.5) P36(13.5,8.5) P37(14.5,8.5) P38(15.5,8.5) P39(16.5,8.5) P40(17.5,8.5) P41(18.5,8.5) P42(19.5,8.5) P43(20.5,8.5) P44(21.5,8.5) R1(-21.5,7.5) R2(-20.5,7.5) R3(-19.5,7.5) R4(-18.5,7.5) R5(-17.5,7.5) R6(-16.5,7.5) R7(-15.5,7.5) R8(-14.5,7.5) R9(-13.5,7.5) R10(-12.5,7.5) R11(-11.5,7.5) R12(-10.5,7.5) R13(-9.5,7.5) R14(-8.5,7.5) R15(-7.5,7.5) R16(-6.5,7.5) R17(-5.5,7.5) R18(-4.5,7.5) R19(-3.5,7.5) R20(-2.5,7.5) R21(-1.5,7.5) R22(-0.5,7.5) R23(0.5,7.5) R24(1.5,7.5) R25(2.5,7.5) R26(3.5,7.5) R27(4.5,7.5) R28(5.5,7.5) R29(6.5,7.5) R30(7.5,7.5) R31(8.5,7.5) R32(9.5,7.5) R33(10.5,7.5) R34(11.5,7.5) R35(12.5,7.5) R36(13.5,7.5) R37(14.5,7.5) R38(15.5,7.5) R39(16.5,7.5) R40(17.5,7.5) R41(18.5,7.5) R42(19.5,7.5) R43(20.5,7.5) R44(21.5,7.5) T1(-21.5,6.5) T2(-20.5,6.5) T3(-19.5,6.5) T4(-18.5,6.5) T5(-17.5,6.5) T6(-16.5,6.5) T7(-15.5,6.5) T8(-14.5,6.5) T9(-13.5,6.5) T10(-12.5,6.5) T11(-11.5,6.5) T12(-10.5,6.5) T13(-9.5,6.5) T14(-8.5,6.5) T15(-7.5,6.5) T16(-6.5,6.5) T17(-5.5,6.5) T18(-4.5,6.5) T19(-3.5,6.5) T20(-2.5,6.5) T21(-1.5,6.5) T22(-0.5,6.5) T23(0.5,6.5) T24(1.5,6.5) T25(2.5,6.5) T26(3.5,6.5) T27(4.5,6.5) T28(5.5,6.5) T29(6.5,6.5) T30(7.5,6.5) T31(8.5,6.5) T32(9.5,6.5) T33(10.5,6.5) T34(11.5,6.5) T35(12.5,6.5) T36(13.5,6.5) T37(14.5,6.5) T38(15.5,6.5) T39(16.5,6.5) T40(17.5,6.5) T41(18.5,6.5) T42(19.5,6.5) T43(20.5,6.5) T44(21.5,6.5) U1(-21.5,5.5) U2(-20.5,5.5) U3(-19.5,5.5) U4(-18.5,5.5) U5(-17.5,5.5) U6(-16.5,5.5) U7(-15.5,5.5) U8(-14.5,5.5) U9(-13.5,5.5) U10(-12.5,5.5) U11(-11.5,5.5) U12(-10.5,5.5) U13(-9.5,5.5) U14(-8.5,5.5) U15(-7.5,5.5) U16(-6.5,5.5) U17(-5.5,5.5) U18(-4.5,5.5) U19(-3.5,5.5) U20(-2.5,5.5) U21(-1.5,5.5) U22(-0.5,5.5) U23(0.5,5.5) U24(1.5,5.5) U25(2.5,5.5) U26(3.5,5.5) U27(4.5,5.5) U28(5.5,5.5) U29(6.5,5.5) U30(7.5,5.5) U31(8.5,5.5) U32(9.5,5.5) U33(10.5,5.5) U34(11.5,5.5) U35(12.5,5.5) U36(13.5,5.5) U37(14.5,5.5) U38(15.5,5.5) U39(16.5,5.5) U40(17.5,5.5) U41(18.5,5.5) U42(19.5,5.5) U43(20.5,5.5) U44(21.5,5.5) V1(-21.5,4.5) V2(-20.5,4.5) V3(-19.5,4.5) V4(-18.5,4.5) V5(-17.5,4.5) V6(-16.5,4.5) V7(-15.5,4.5) V8(-14.5,4.5) V9(-13.5,4.5) V10(-12.5,4.5) V11(-11.5,4.5) V12(-10.5,4.5) V13(-9.5,4.5) V14(-8.5,4.5) V15(-7.5,4.5) V16(-6.5,4.5) V17(-5.5,4.5) V18(-4.5,4.5) V19(-3.5,4.5) V20(-2.5,4.5) V21(-1.5,4.5) V22(-0.5,4.5) V23(0.5,4.5) V24(1.5,4.5) V25(2.5,4.5) V26(3.5,4.5) V27(4.5,4.5) V28(5.5,4.5) V29(6.5,4.5) V30(7.5,4.5) V31(8.5,4.5) V32(9.5,4.5) V33(10.5,4.5) V34(11.5,4.5) V35(12.5,4.5) V36(13.5,4.5) V37(14.5,4.5) V38(15.5,4.5) V39(16.5,4.5) V40(17.5,4.5) V41(18.5,4.5) V42(19.5,4.5) V43(20.5,4.5) V44(21.5,4.5) W1(-21.5,3.5) W2(-20.5,3.5) W3(-19.5,3.5) W4(-18.5,3.5) W5(-17.5,3.5) W6(-16.5,3.5) W7(-15.5,3.5) W8(-14.5,3.5) W9(-13.5,3.5) W10(-12.5,3.5) W11(-11.5,3.5) W12(-10.5,3.5) W13(-9.5,3.5) W14(-8.5,3.5) W15(-7.5,3.5) W16(-6.5,3.5) W17(-5.5,3.5) W18(-4.5,3.5) W19(-3.5,3.5) W20(-2.5,3.5) W21(-1.5,3.5) W22(-0.5,3.5) W23(0.5,3.5) W24(1.5,3.5) W25(2.5,3.5) W26(3.5,3.5) W27(4.5,3.5) W28(5.5,3.5) W29(6.5,3.5) W30(7.5,3.5) W31(8.5,3.5) W32(9.5,3.5) W33(10.5,3.5) W34(11.5,3.5) W35(12.5,3.5) W36(13.5,3.5) W37(14.5,3.5) W38(15.5,3.5) W39(16.5,3.5) W40(17.5,3.5) W41(18.5,3.5) W42(19.5,3.5) W43(20.5,3.5) W44(21.5,3.5) Y1(-21.5,2.5) Y2(-20.5,2.5) Y3(-19.5,2.5) Y4(-18.5,2.5) Y5(-17.5,2.5) Y6(-16.5,2.5) Y7(-15.5,2.5) Y8(-14.5,2.5) Y9(-13.5,2.5) Y10(-12.5,2.5) Y11(-11.5,2.5) Y12(-10.5,2.5) Y13(-9.5,2.5) Y14(-8.5,2.5) Y15(-7.5,2.5) Y16(-6.5,2.5) Y17(-5.5,2.5) Y18(-4.5,2.5) Y19(-3.5,2.5) Y20(-2.5,2.5) Y21(-1.5,2.5) Y22(-0.5,2.5) Y23(0.5,2.5) Y24(1.5,2.5) Y25(2.5,2.5) Y26(3.5,2.5) Y27(4.5,2.5) Y28(5.5,2.5) Y29(6.5,2.5) Y30(7.5,2.5) Y31(8.5,2.5) Y32(9.5,2.5) Y33(10.5,2.5) Y34(11.5,2.5) Y35(12.5,2.5) Y36(13.5,2.5) Y37(14.5,2.5) Y38(15.5,2.5) Y39(16.5,2.5) Y40(17.5,2.5) Y41(18.5,2.5) Y42(19.5,2.5) Y43(20.5,2.5) Y44(21.5,2.5)
